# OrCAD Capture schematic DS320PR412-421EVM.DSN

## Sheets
1 PAGE1: title: DS320PR412-421EVM Block; rev: A; note: HSDC110A
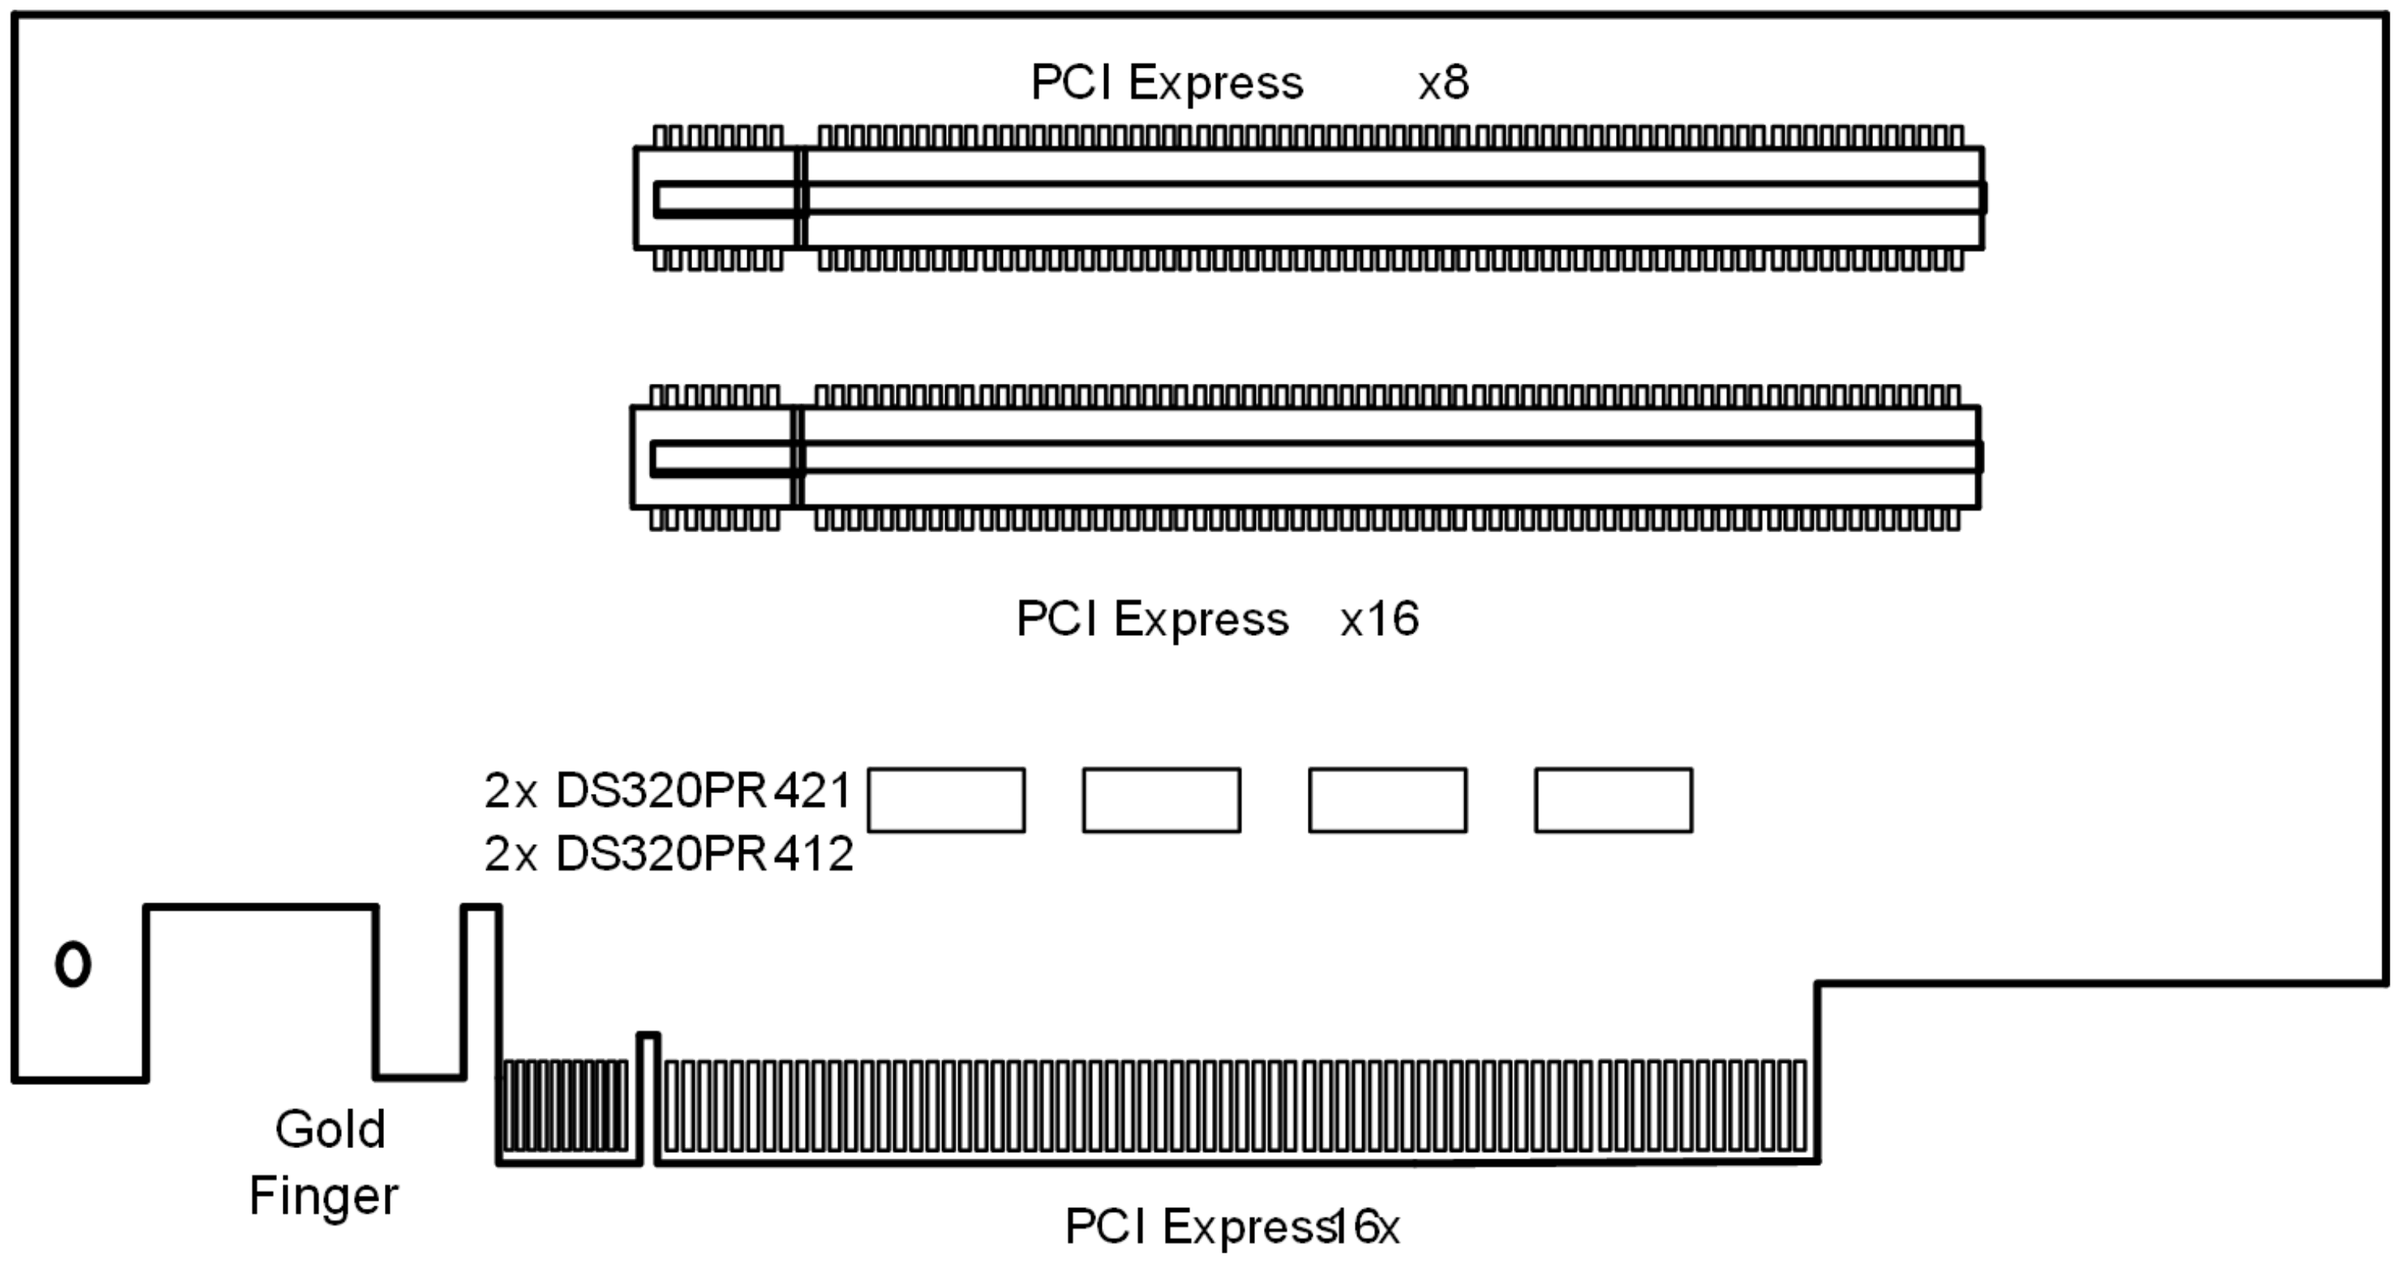
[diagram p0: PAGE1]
2 PAGE10: size C; title: PCIe Connector B x16
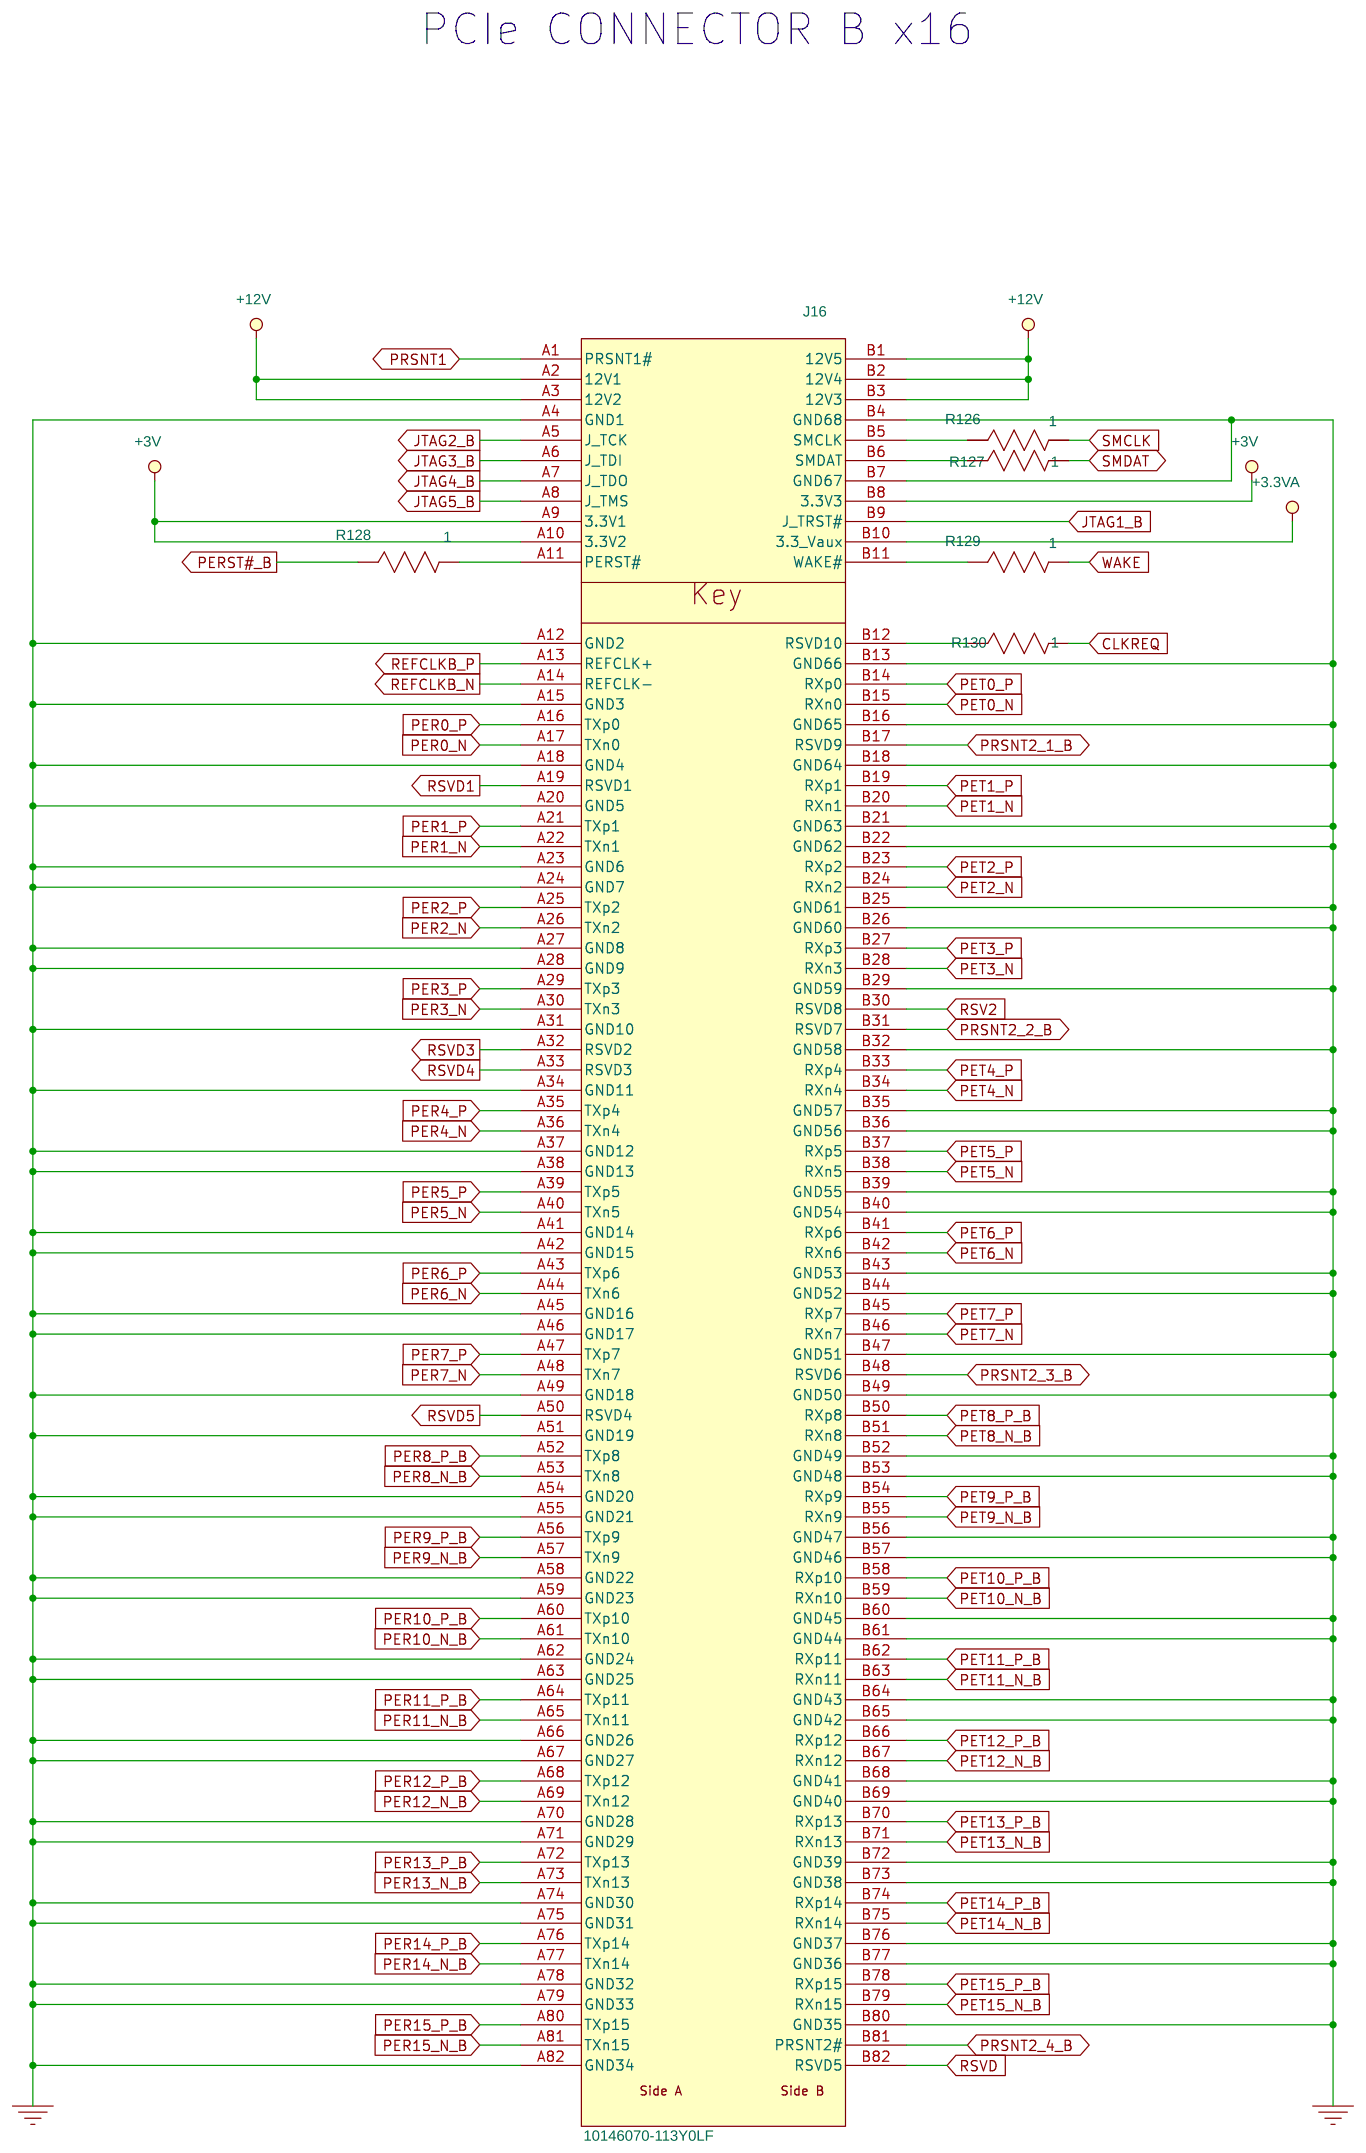
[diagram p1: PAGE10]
3 PAGE11: title: Hardware
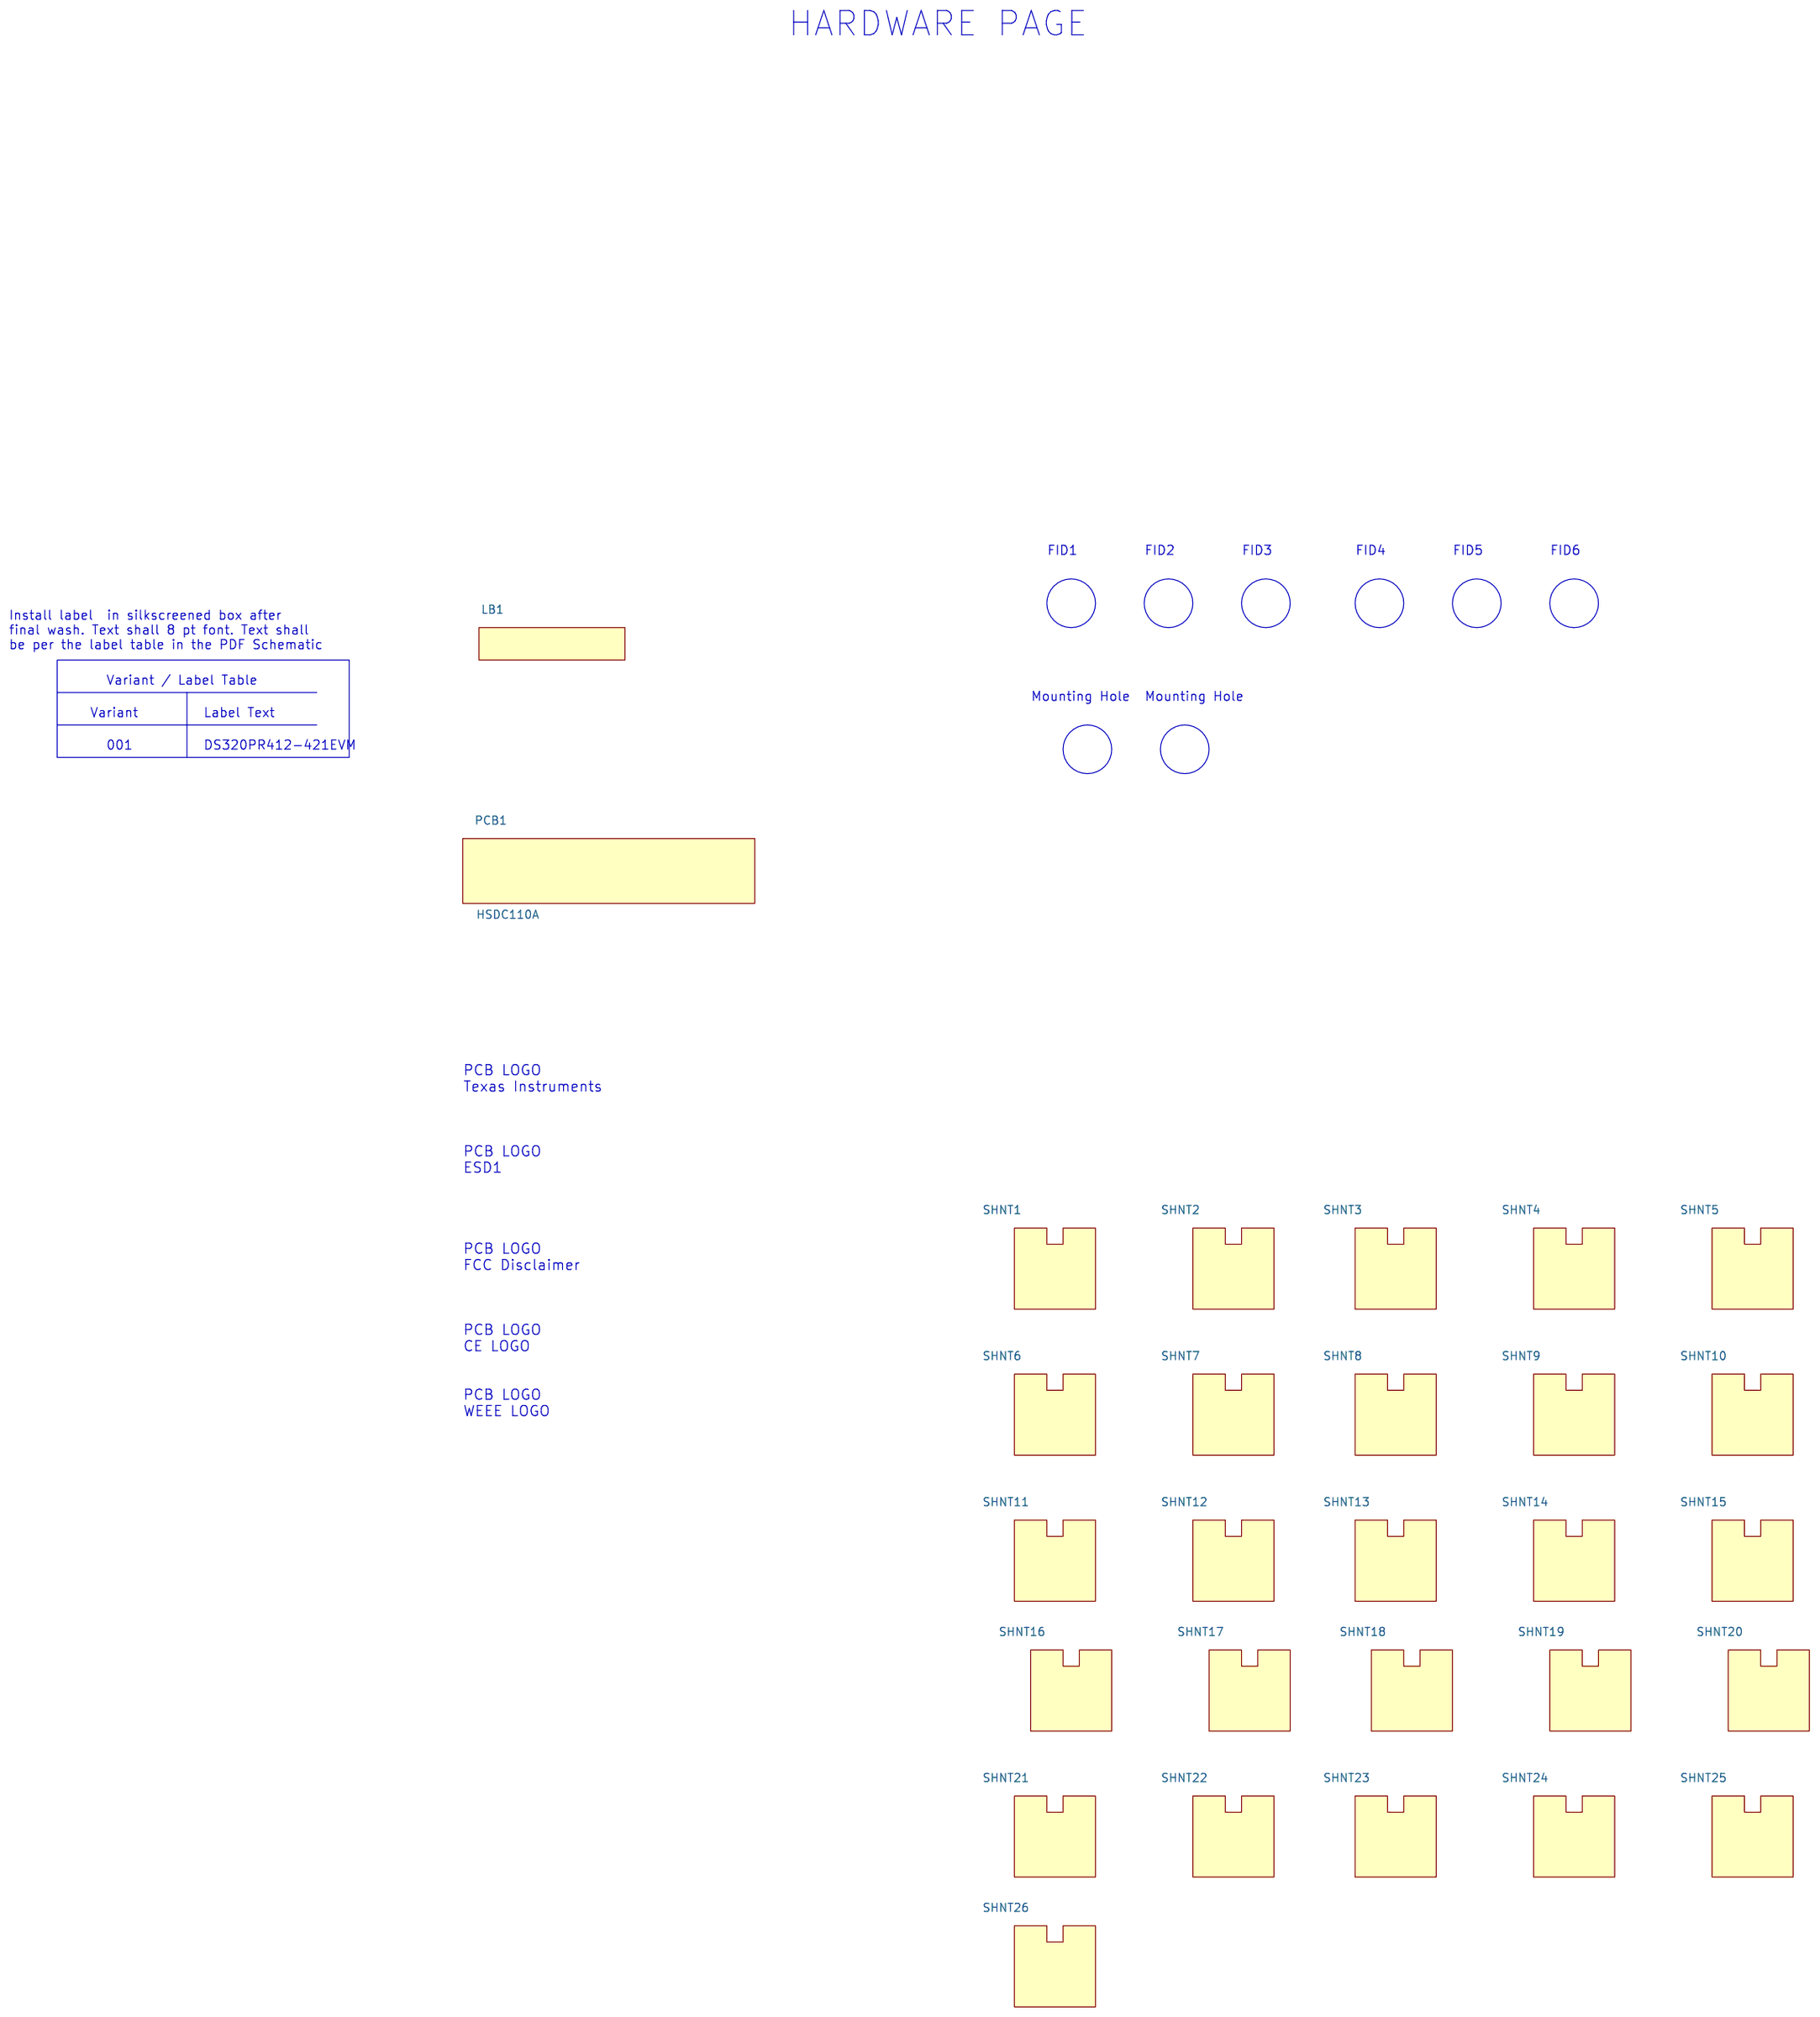
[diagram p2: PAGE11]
4 PAGE2: size C; title: DS320PR412
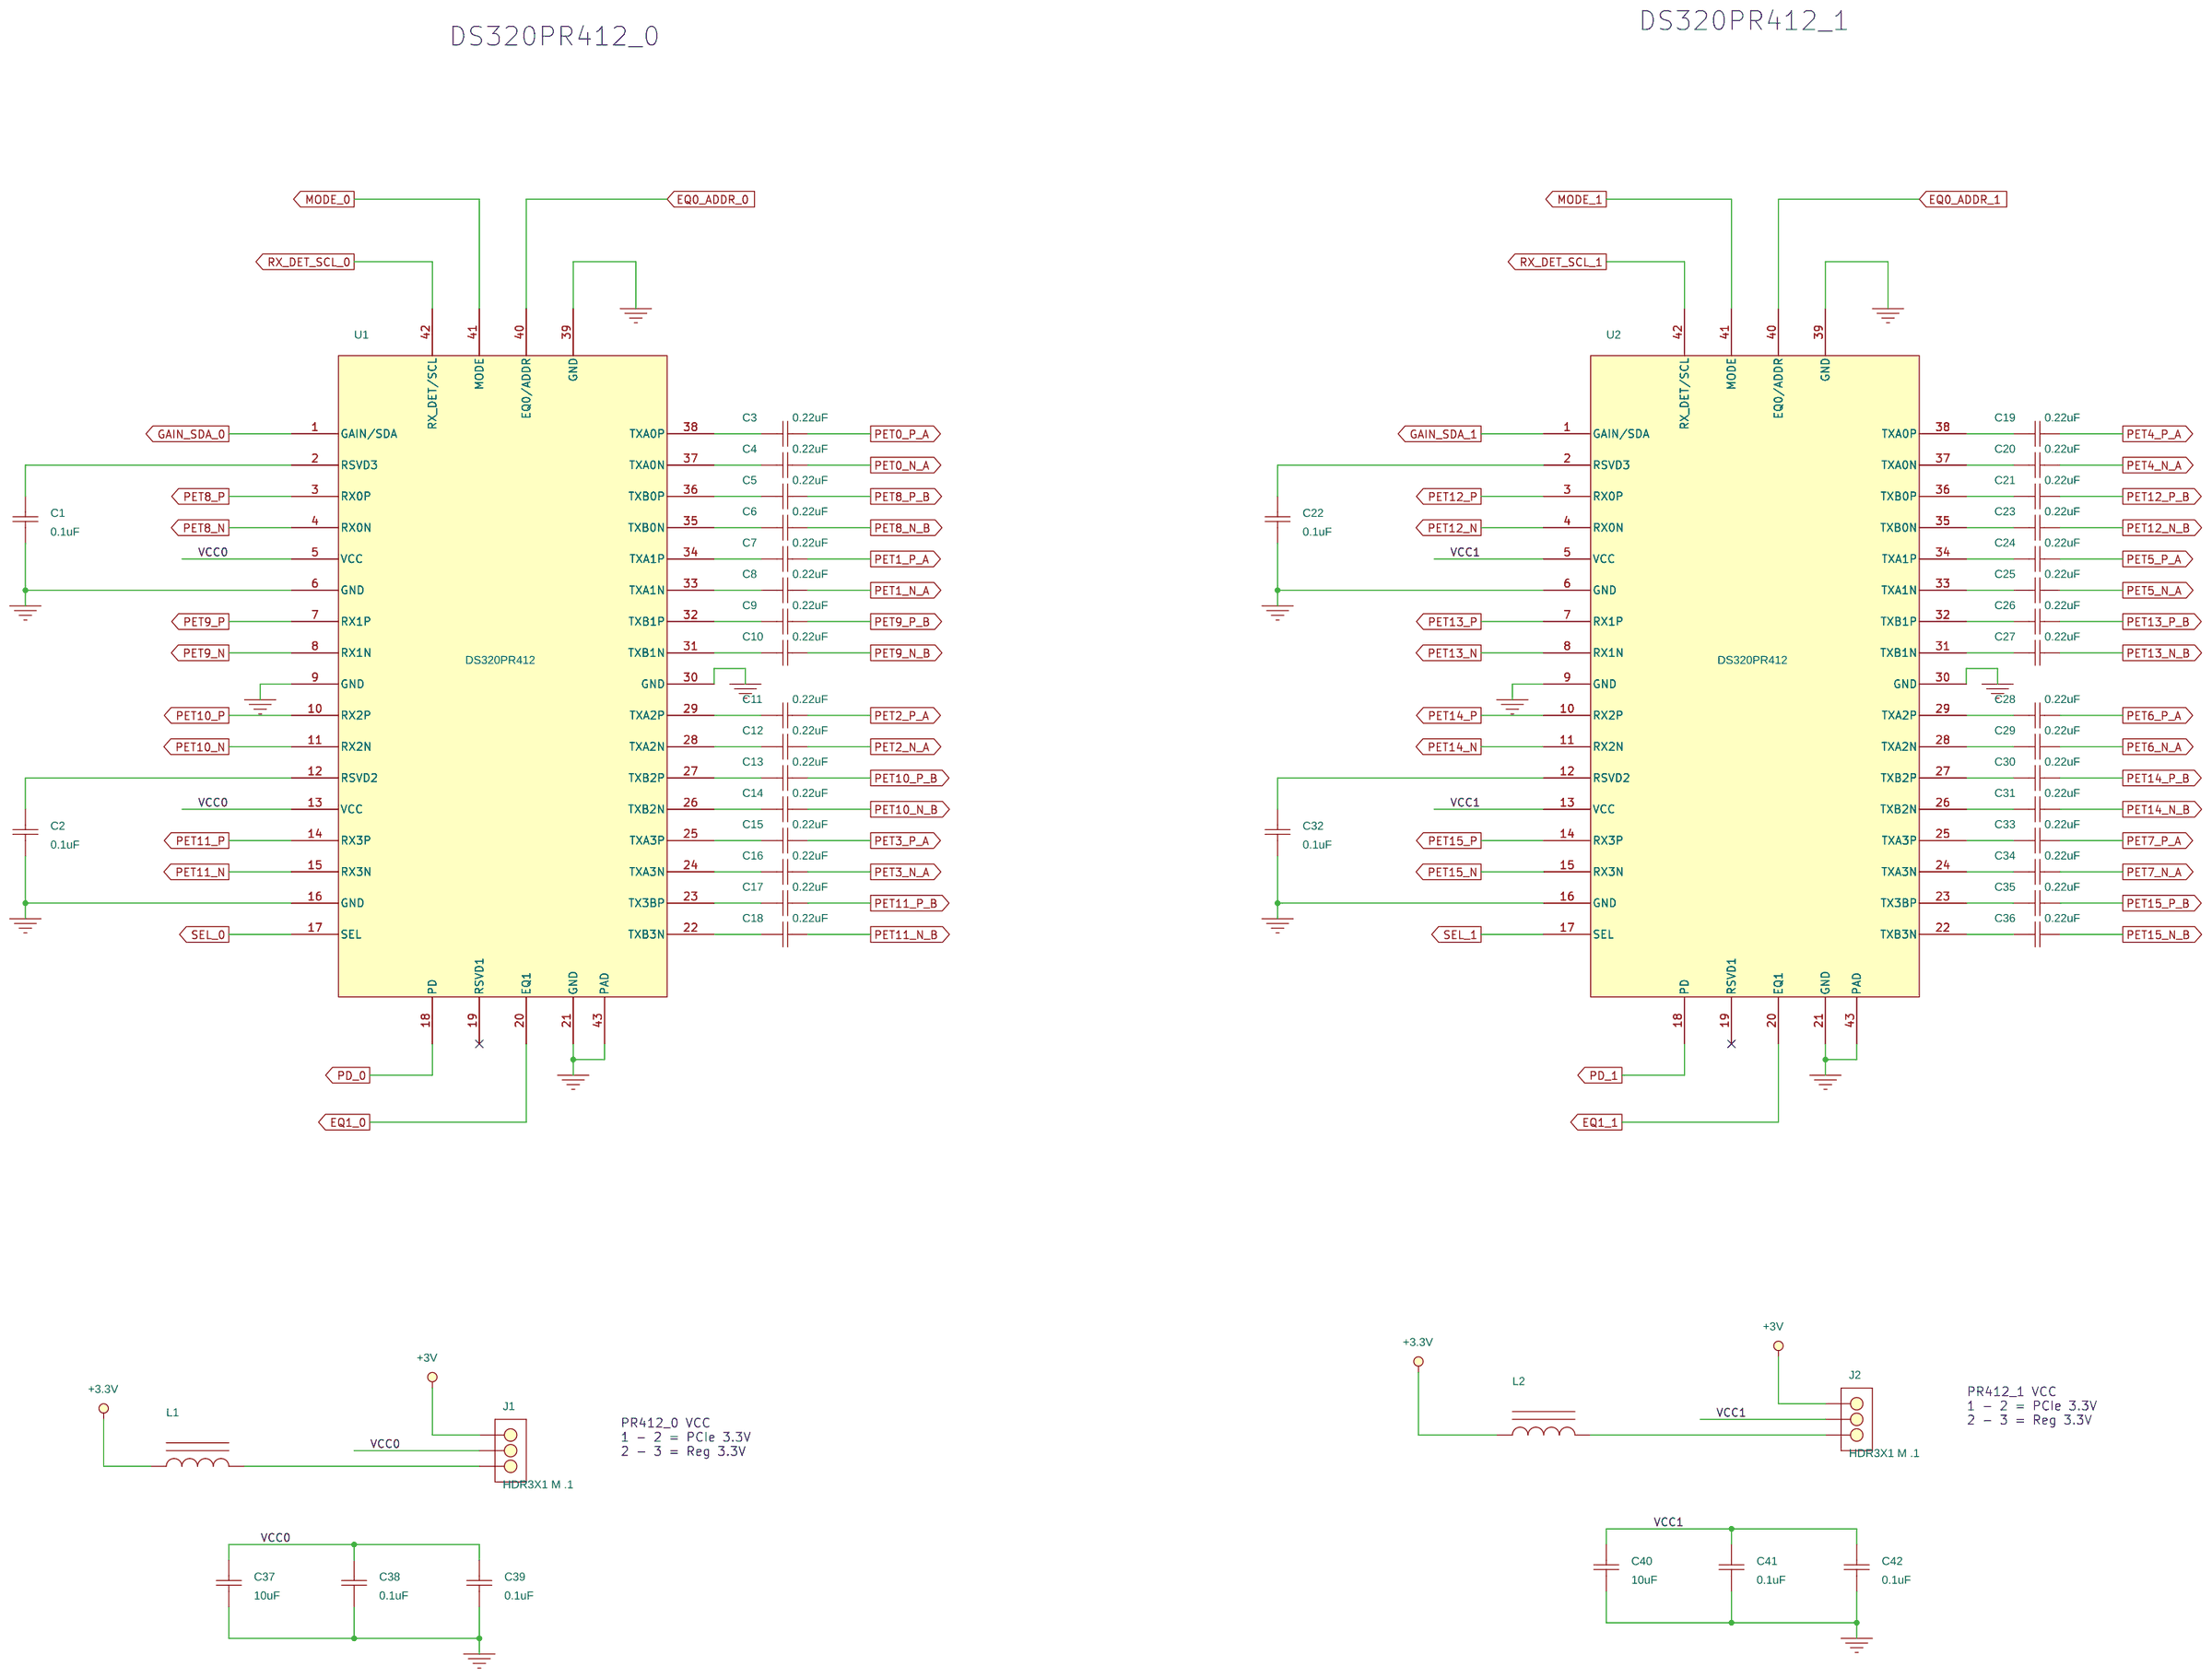
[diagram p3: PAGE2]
5 PAGE3: size C; title: DS320PR421
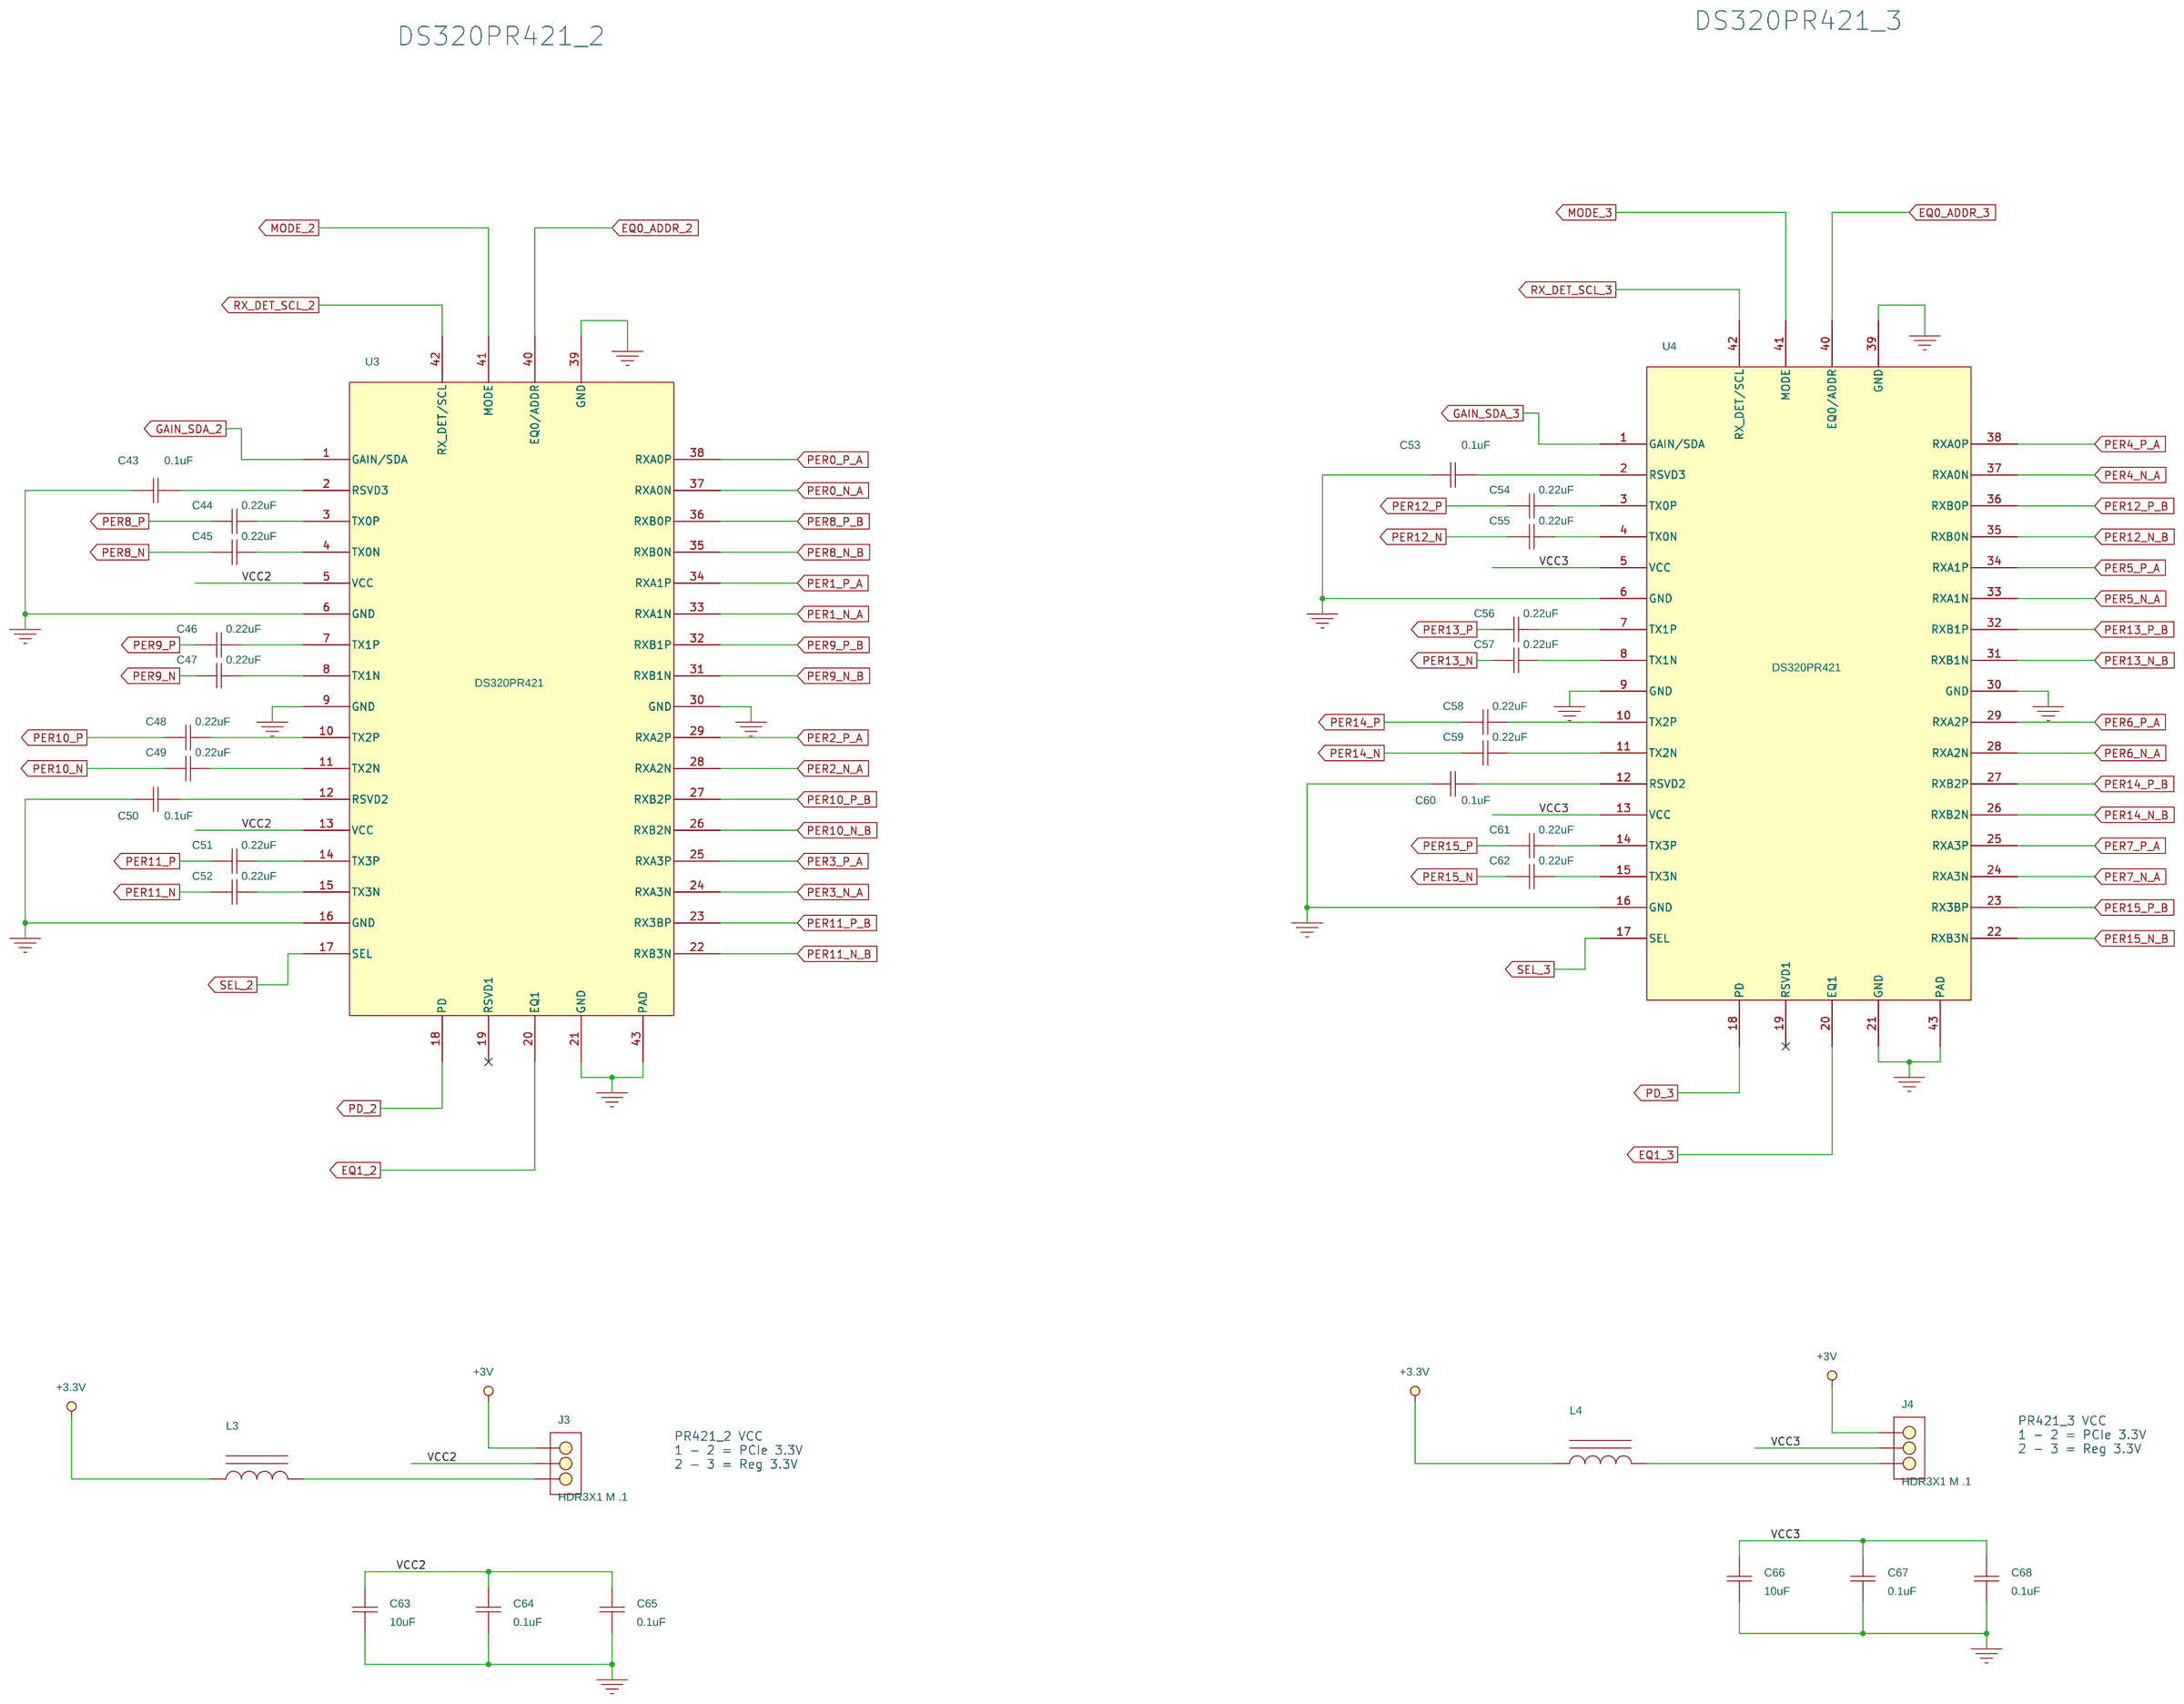
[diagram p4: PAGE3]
6 PAGE4: size C; title: DS320PR412-421 CONFIG
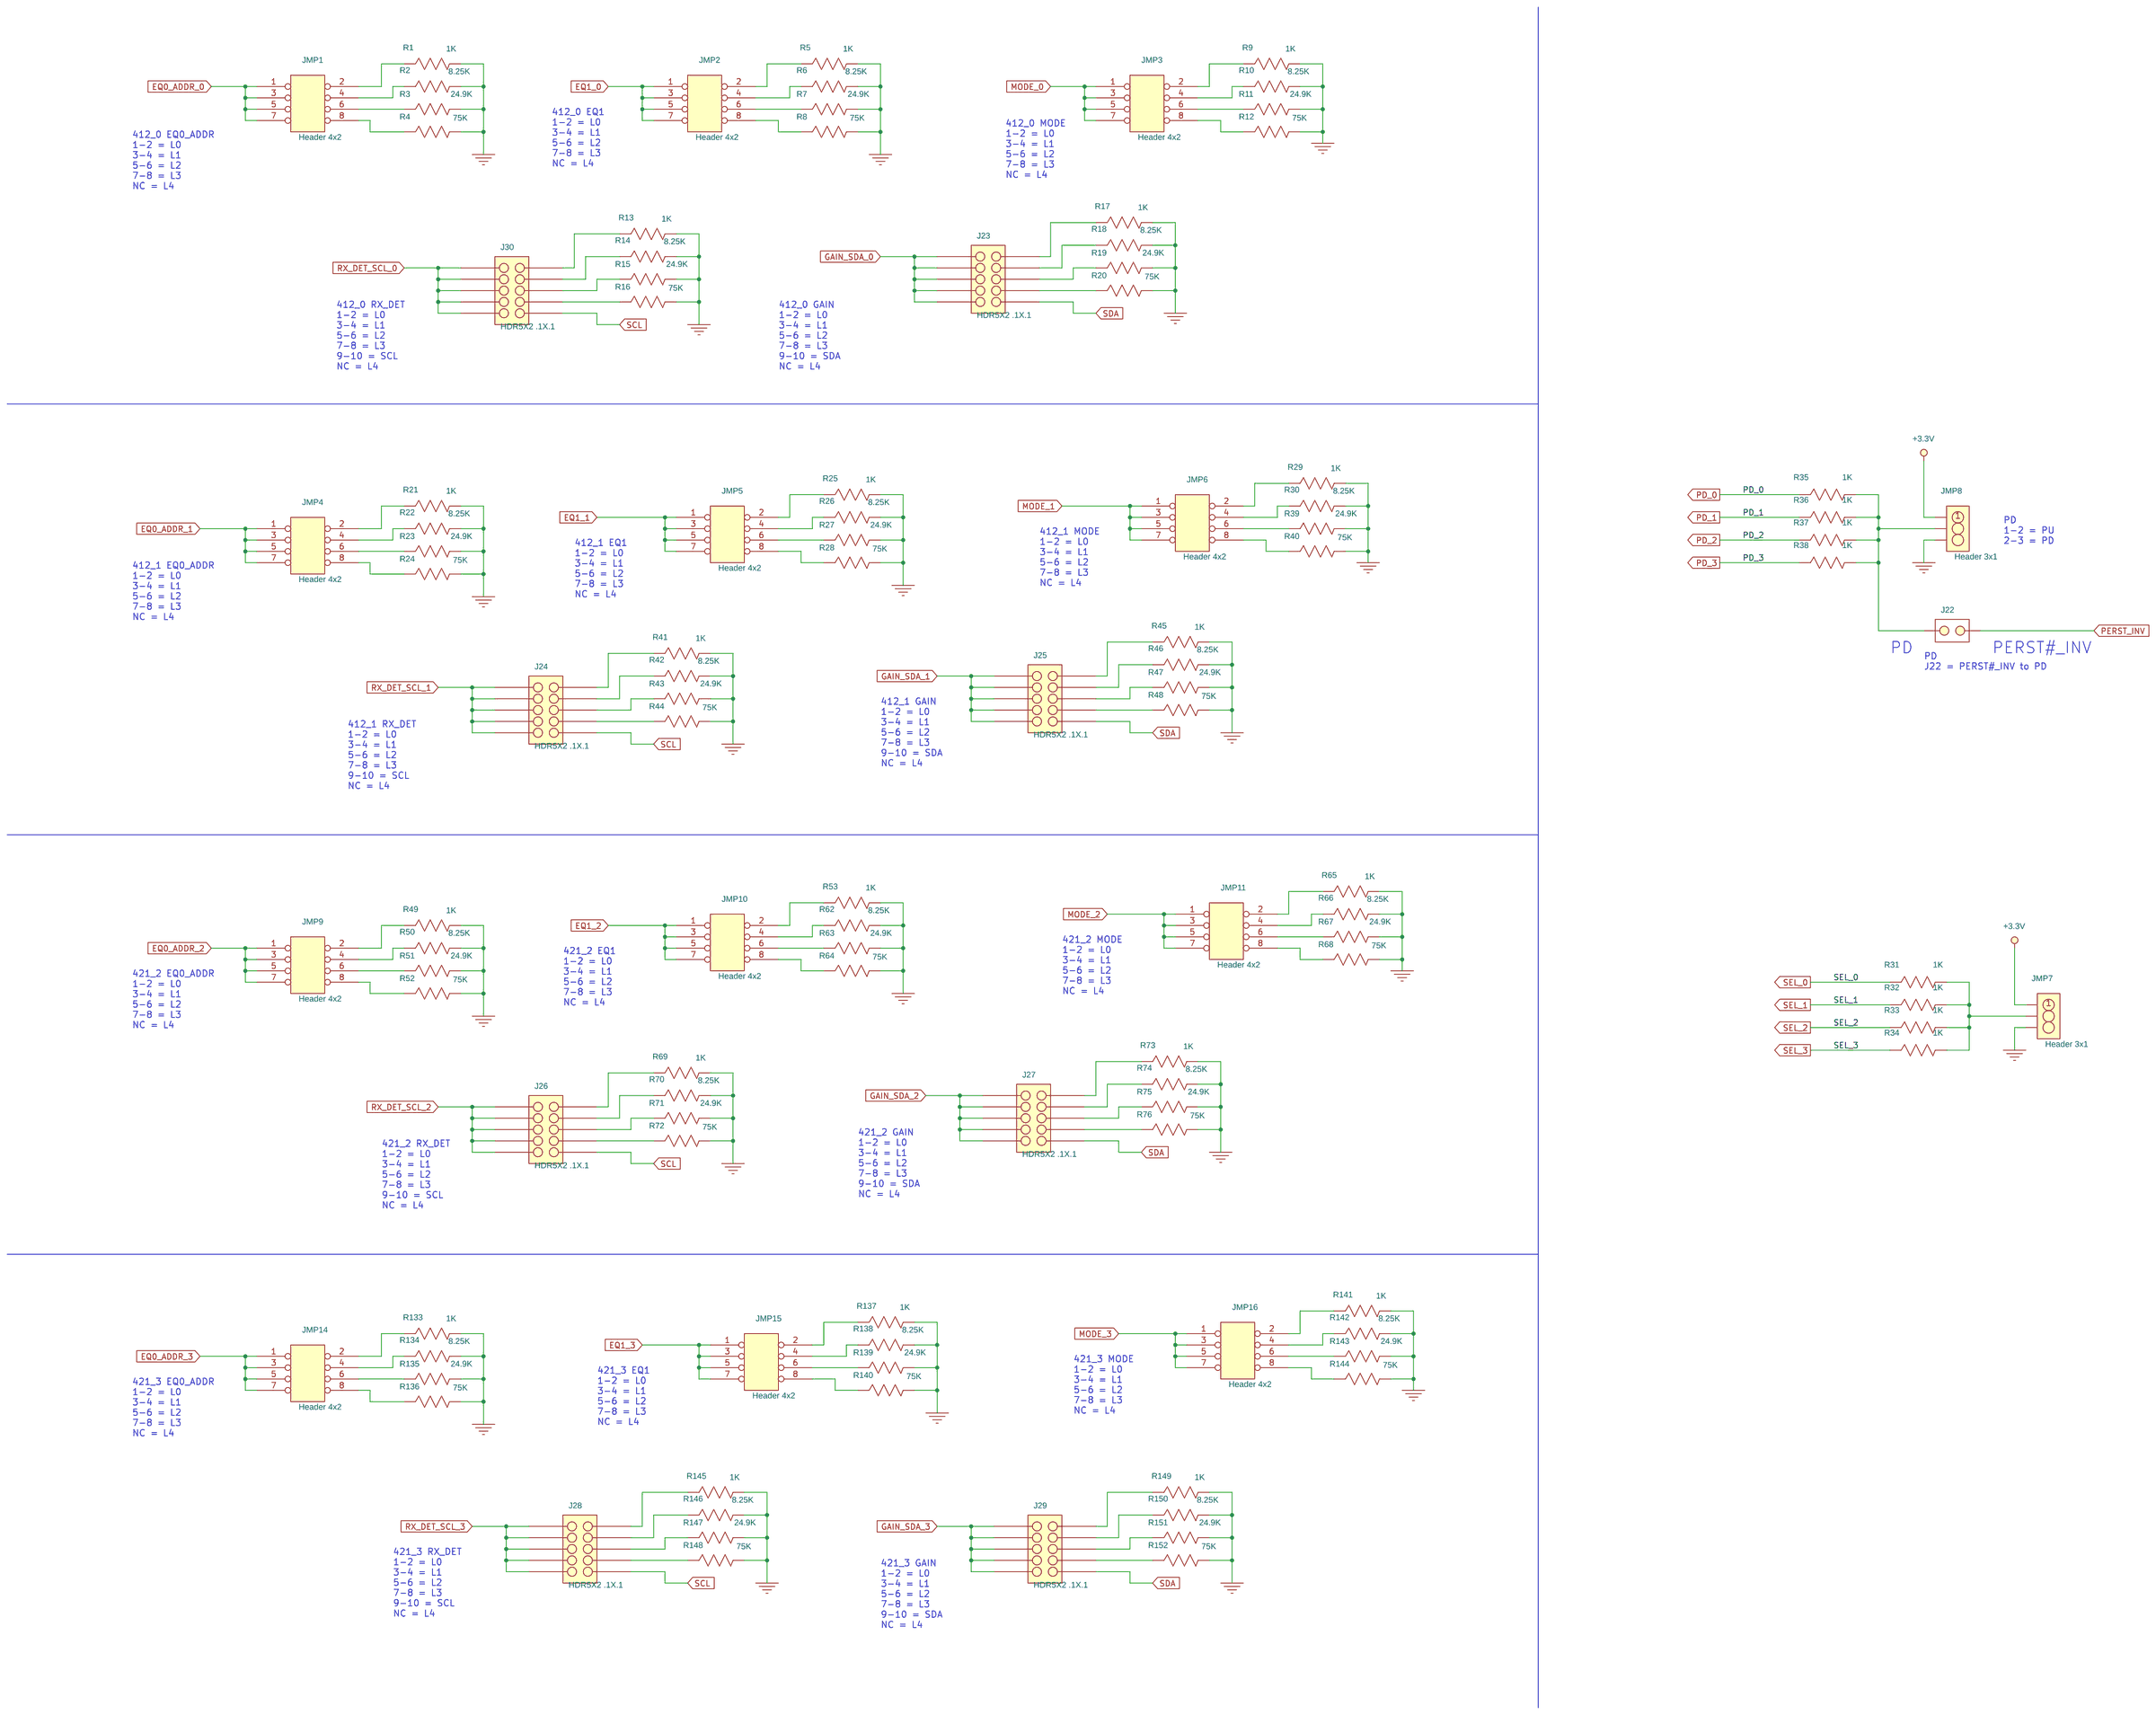
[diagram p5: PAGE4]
7 PAGE5: size C; title: I2C / JTAG
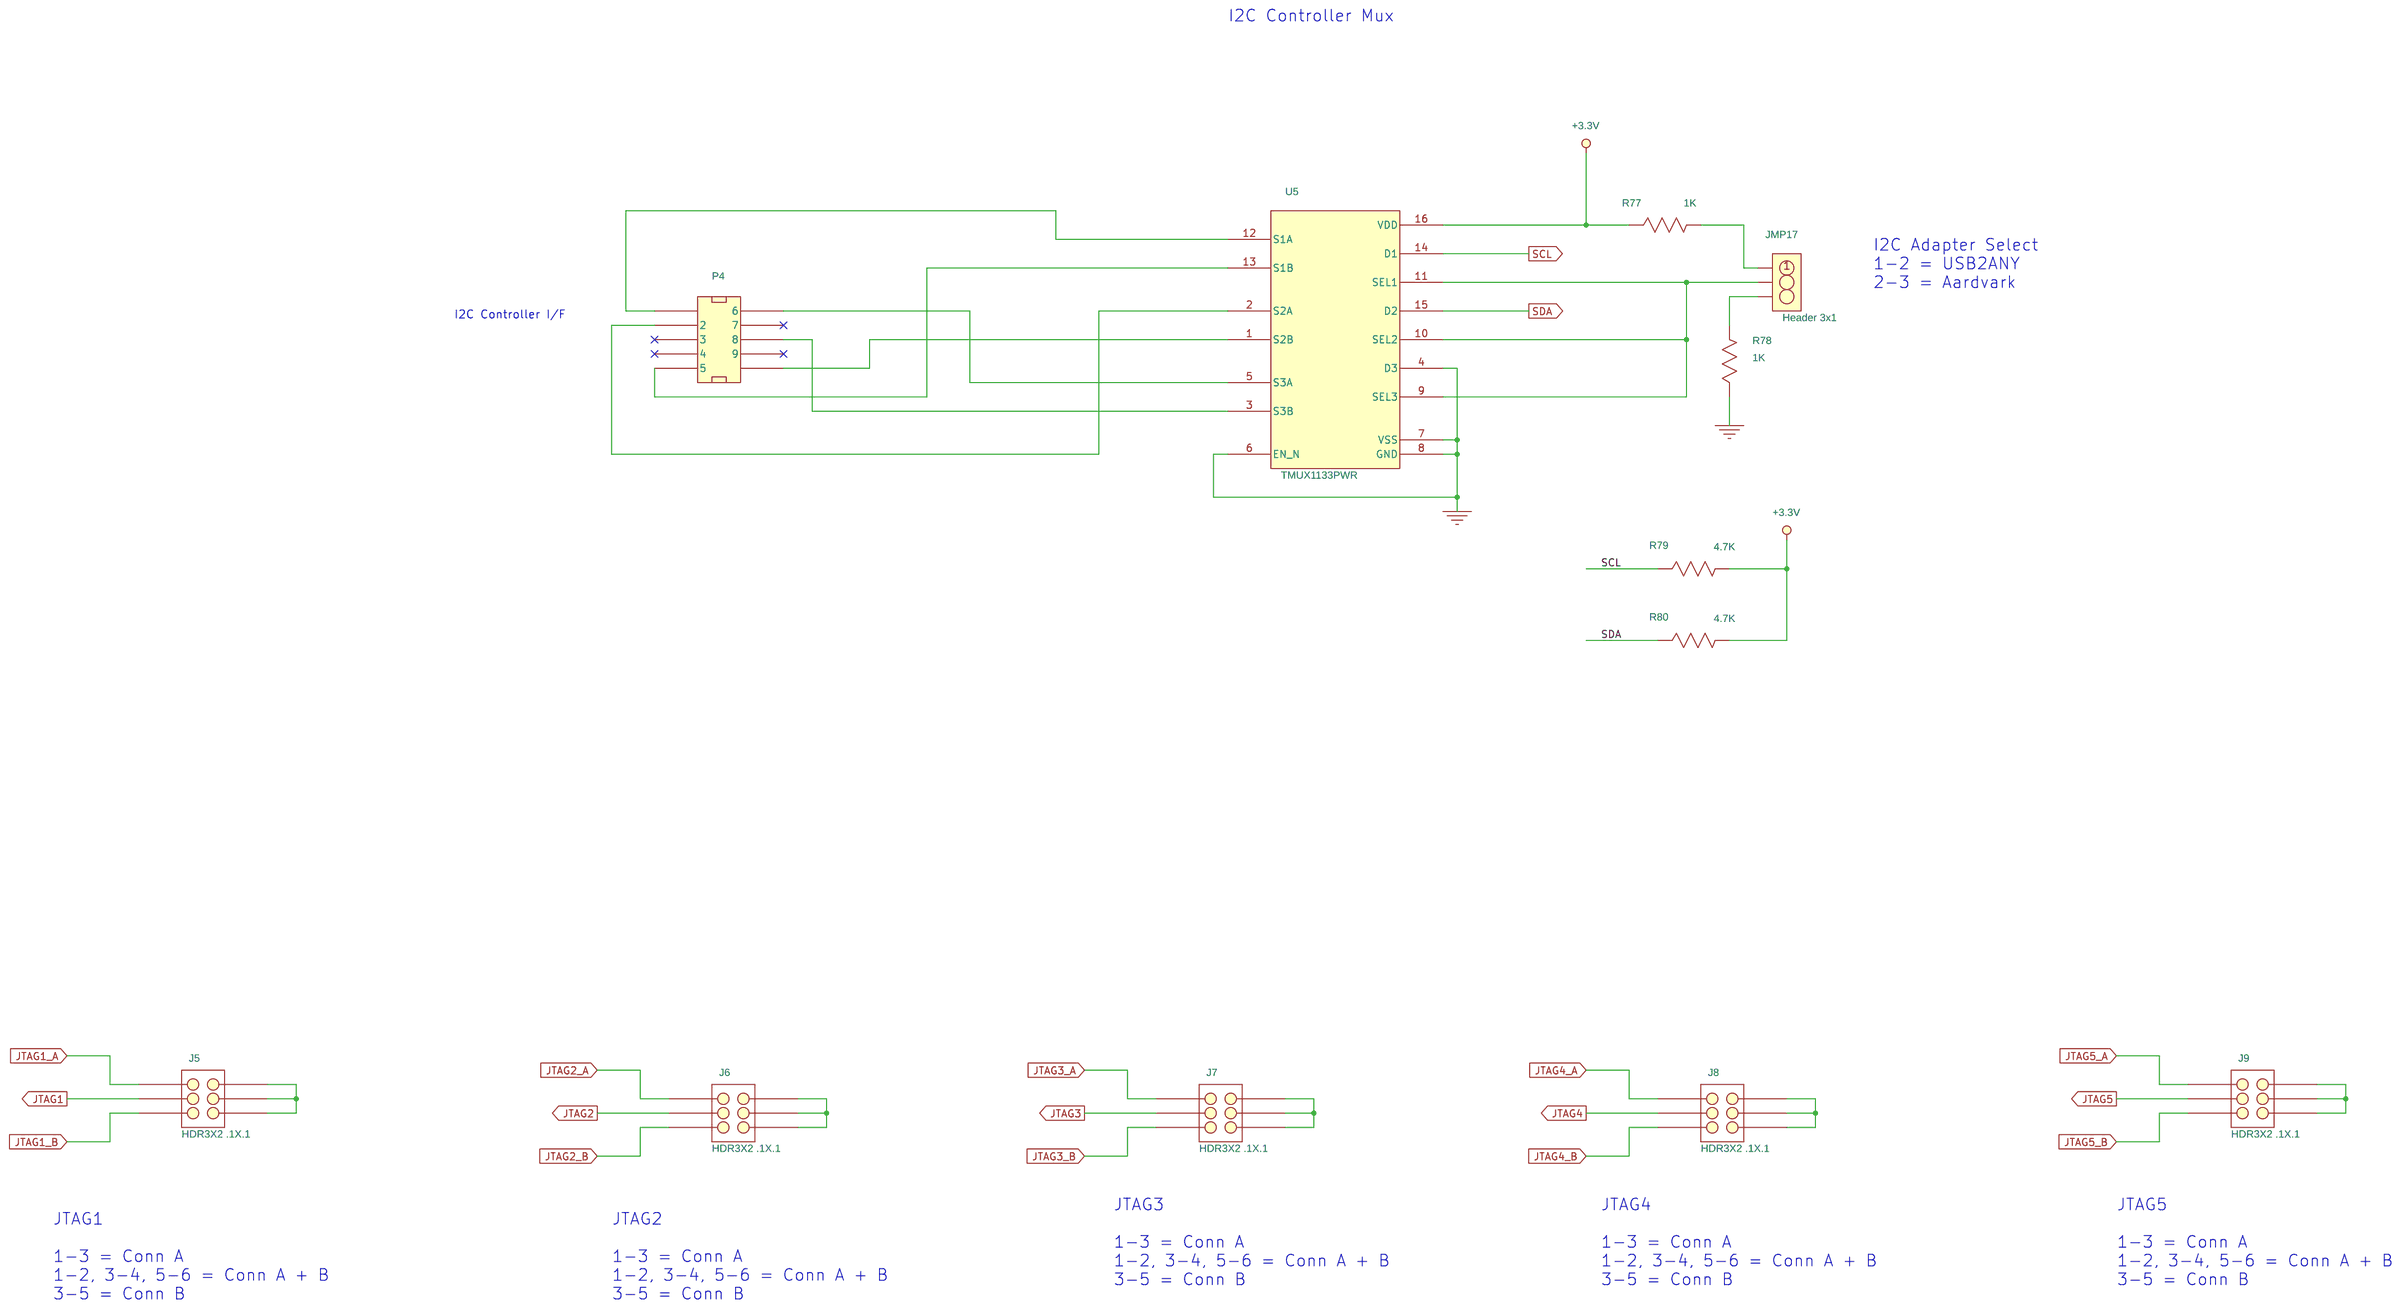
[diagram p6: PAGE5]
8 PAGE6: size C; title: POWER
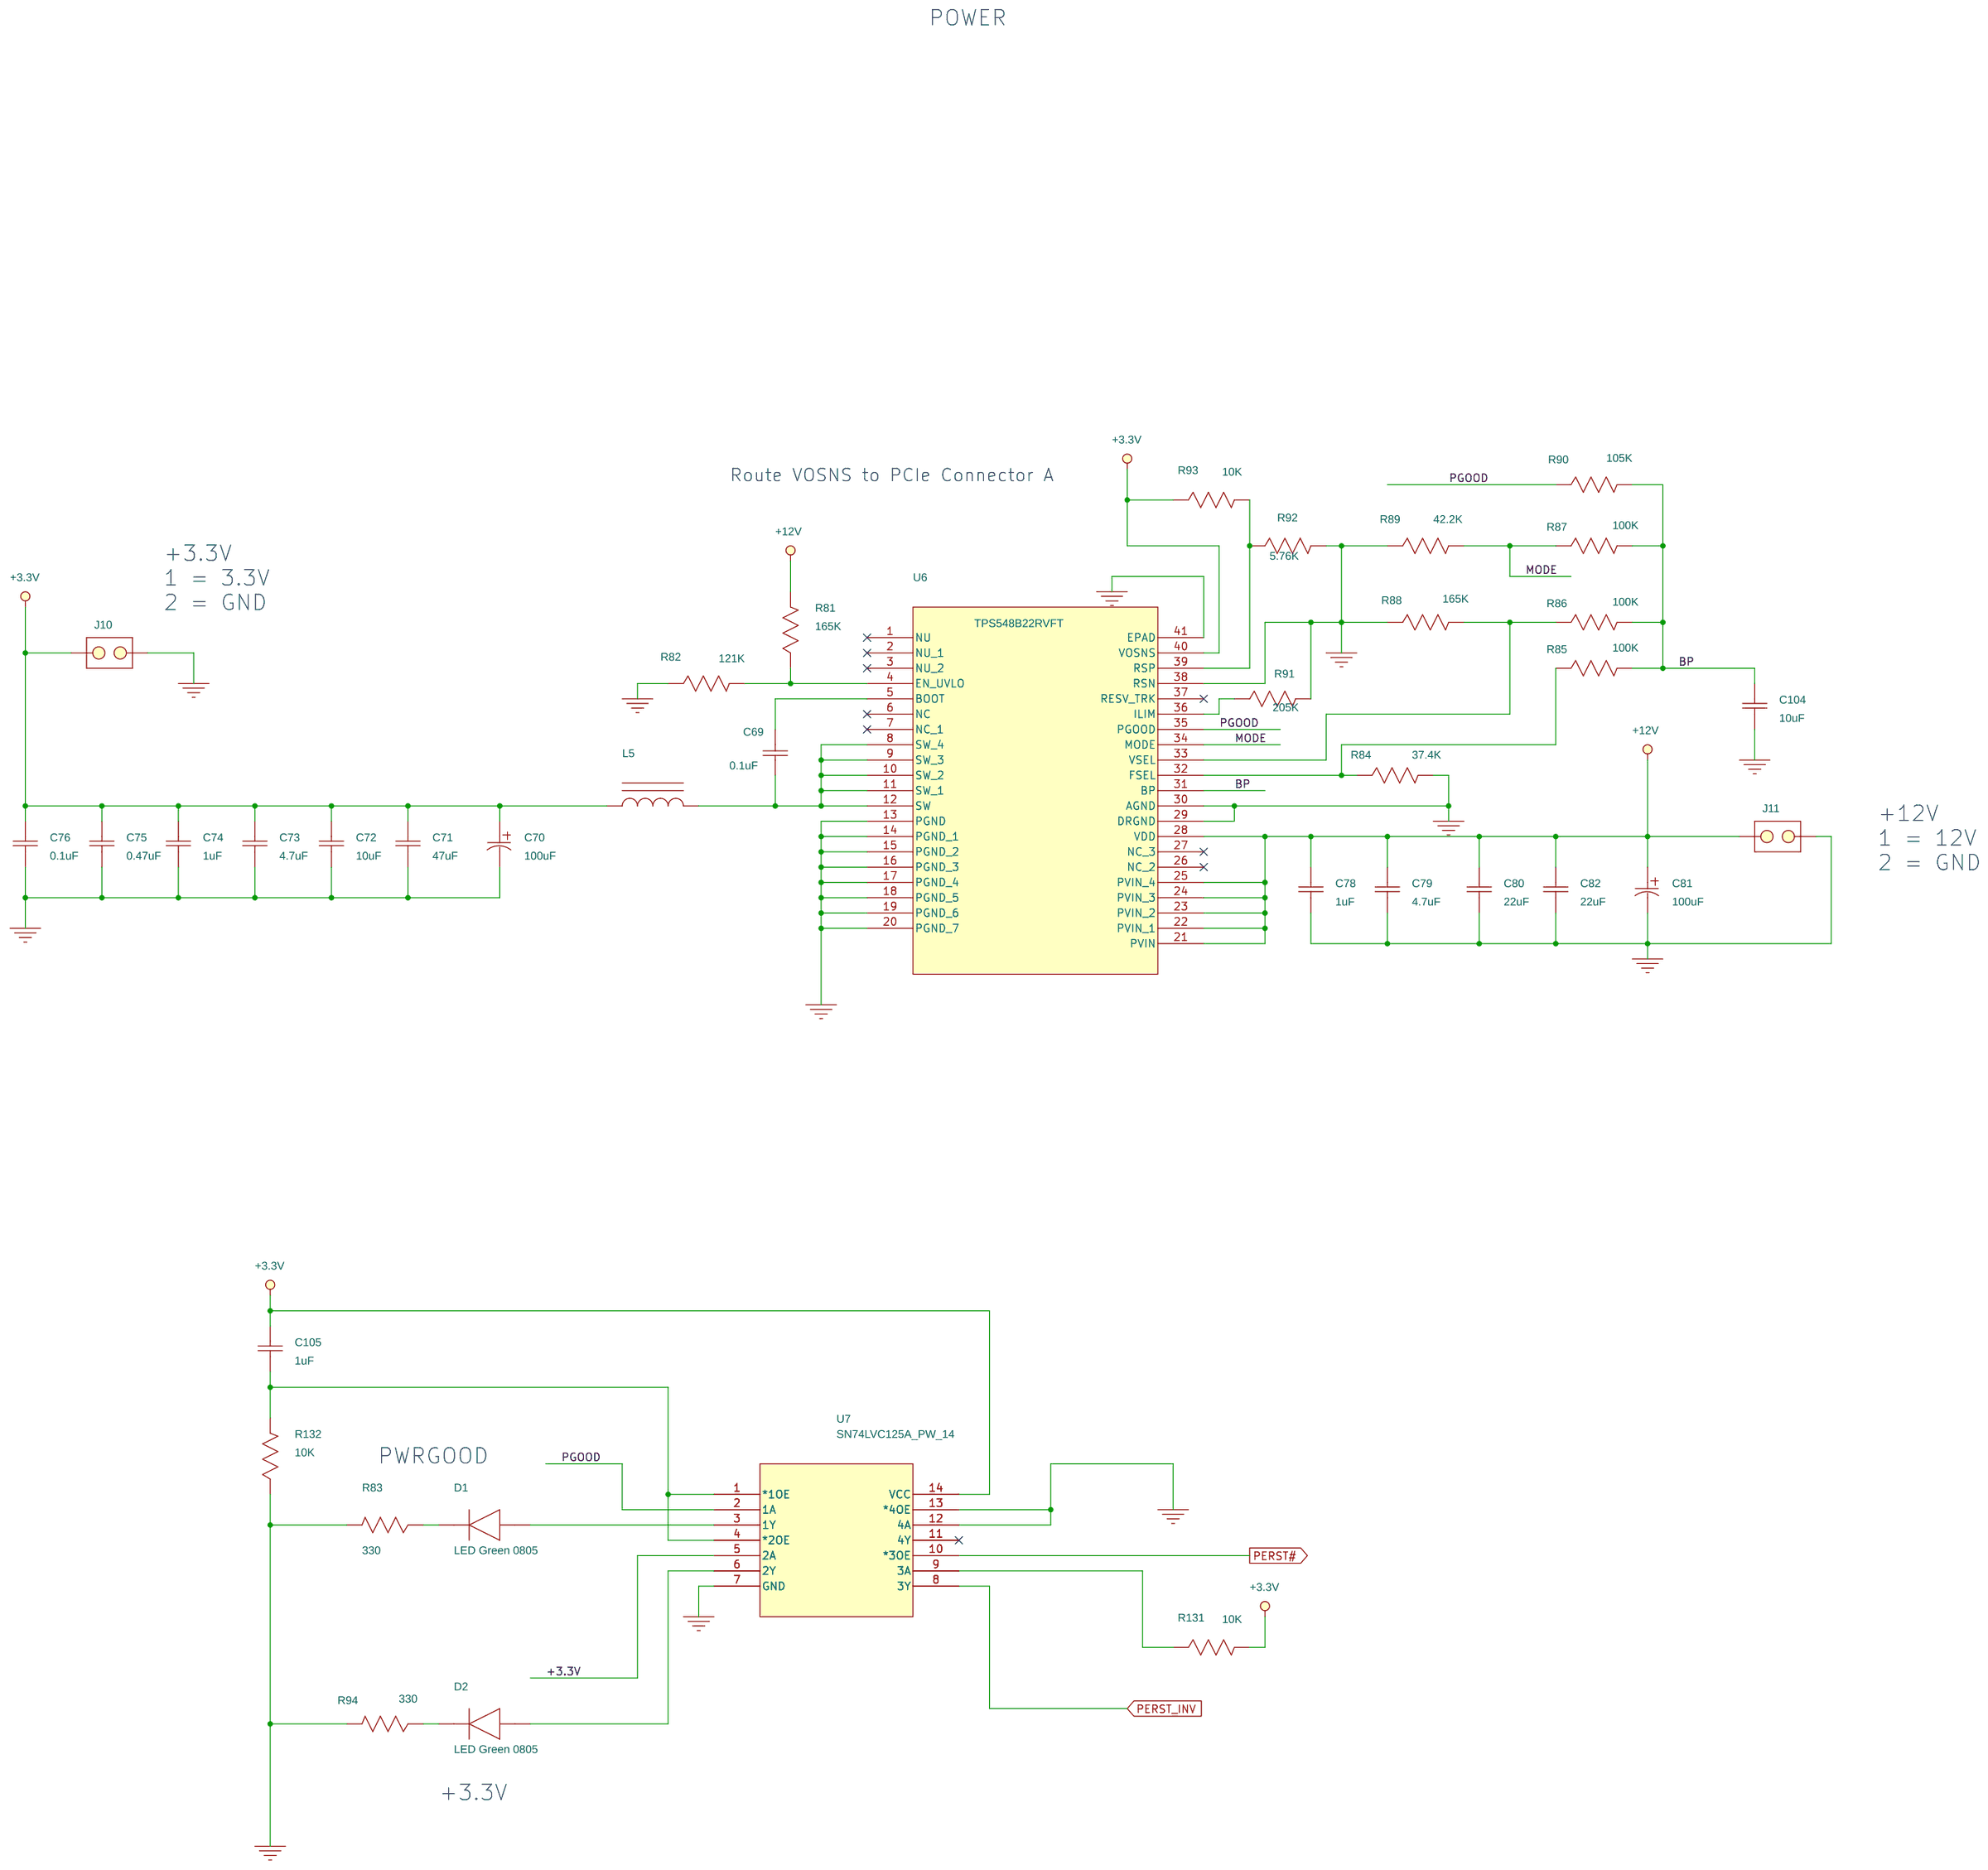
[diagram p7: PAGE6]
9 PAGE7: size C; title: PCIe EDGE Connector
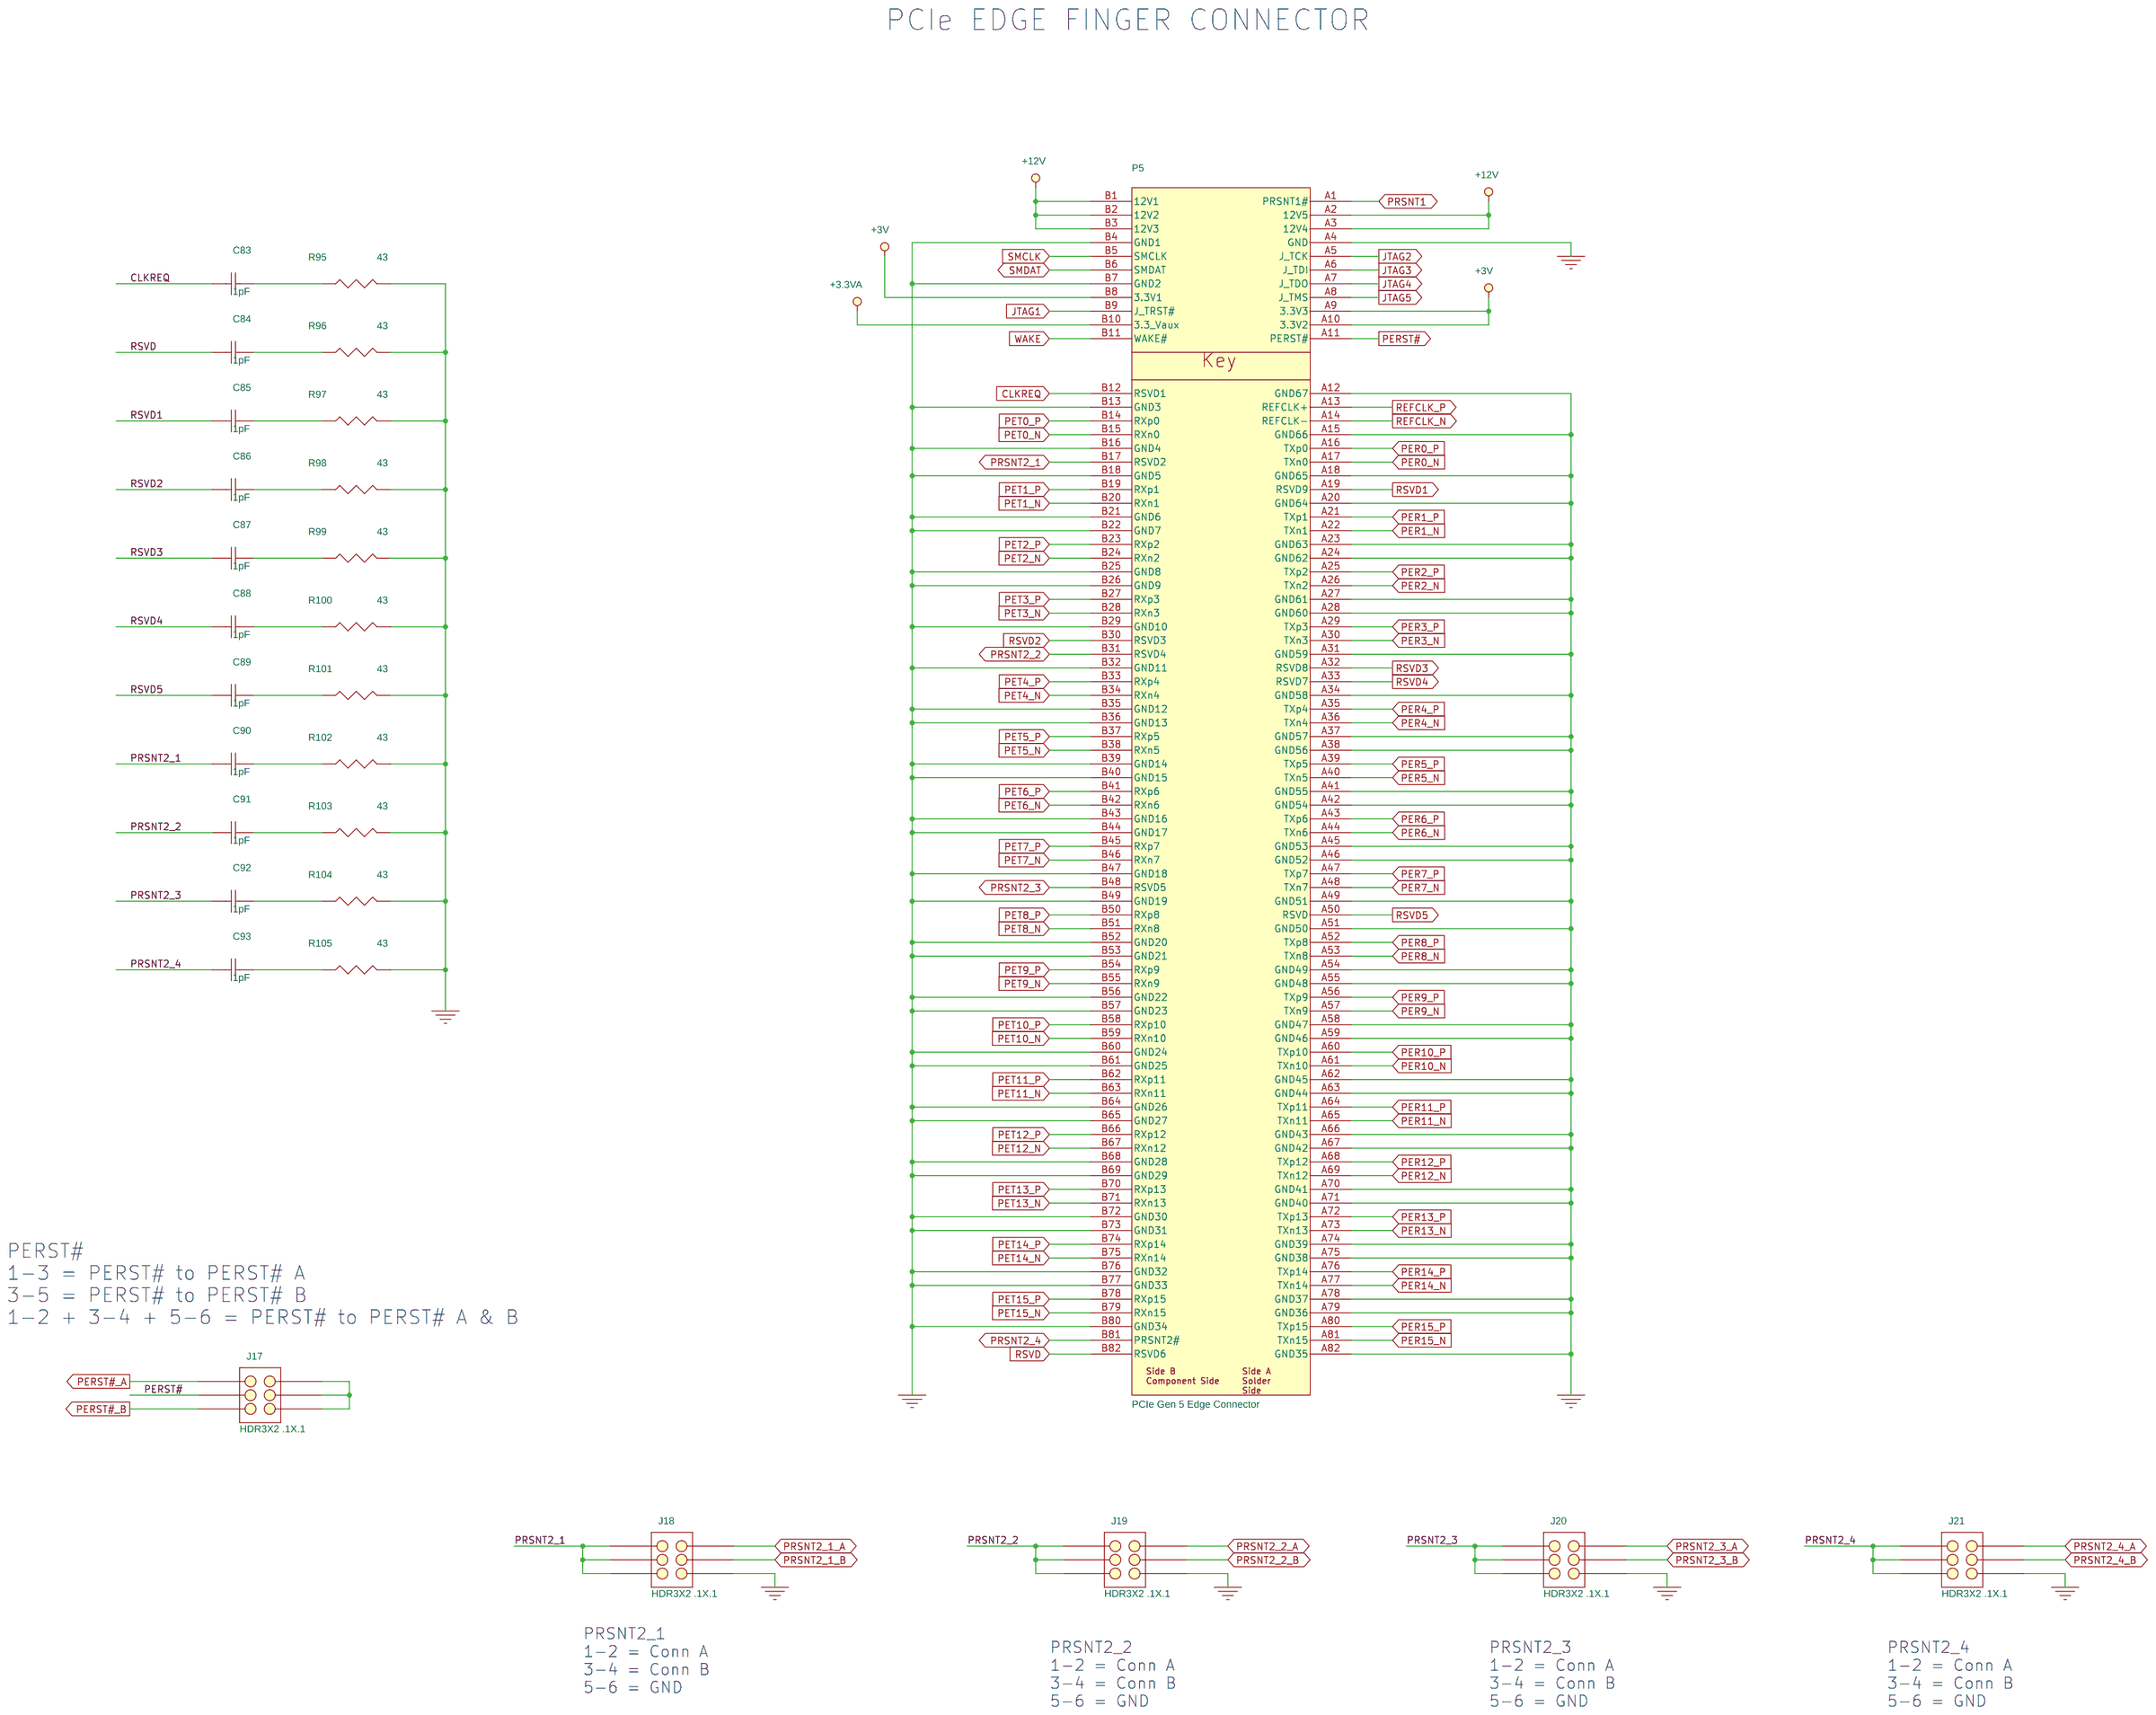
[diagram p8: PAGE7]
10 PAGE8: size C; title: CLK Buffer
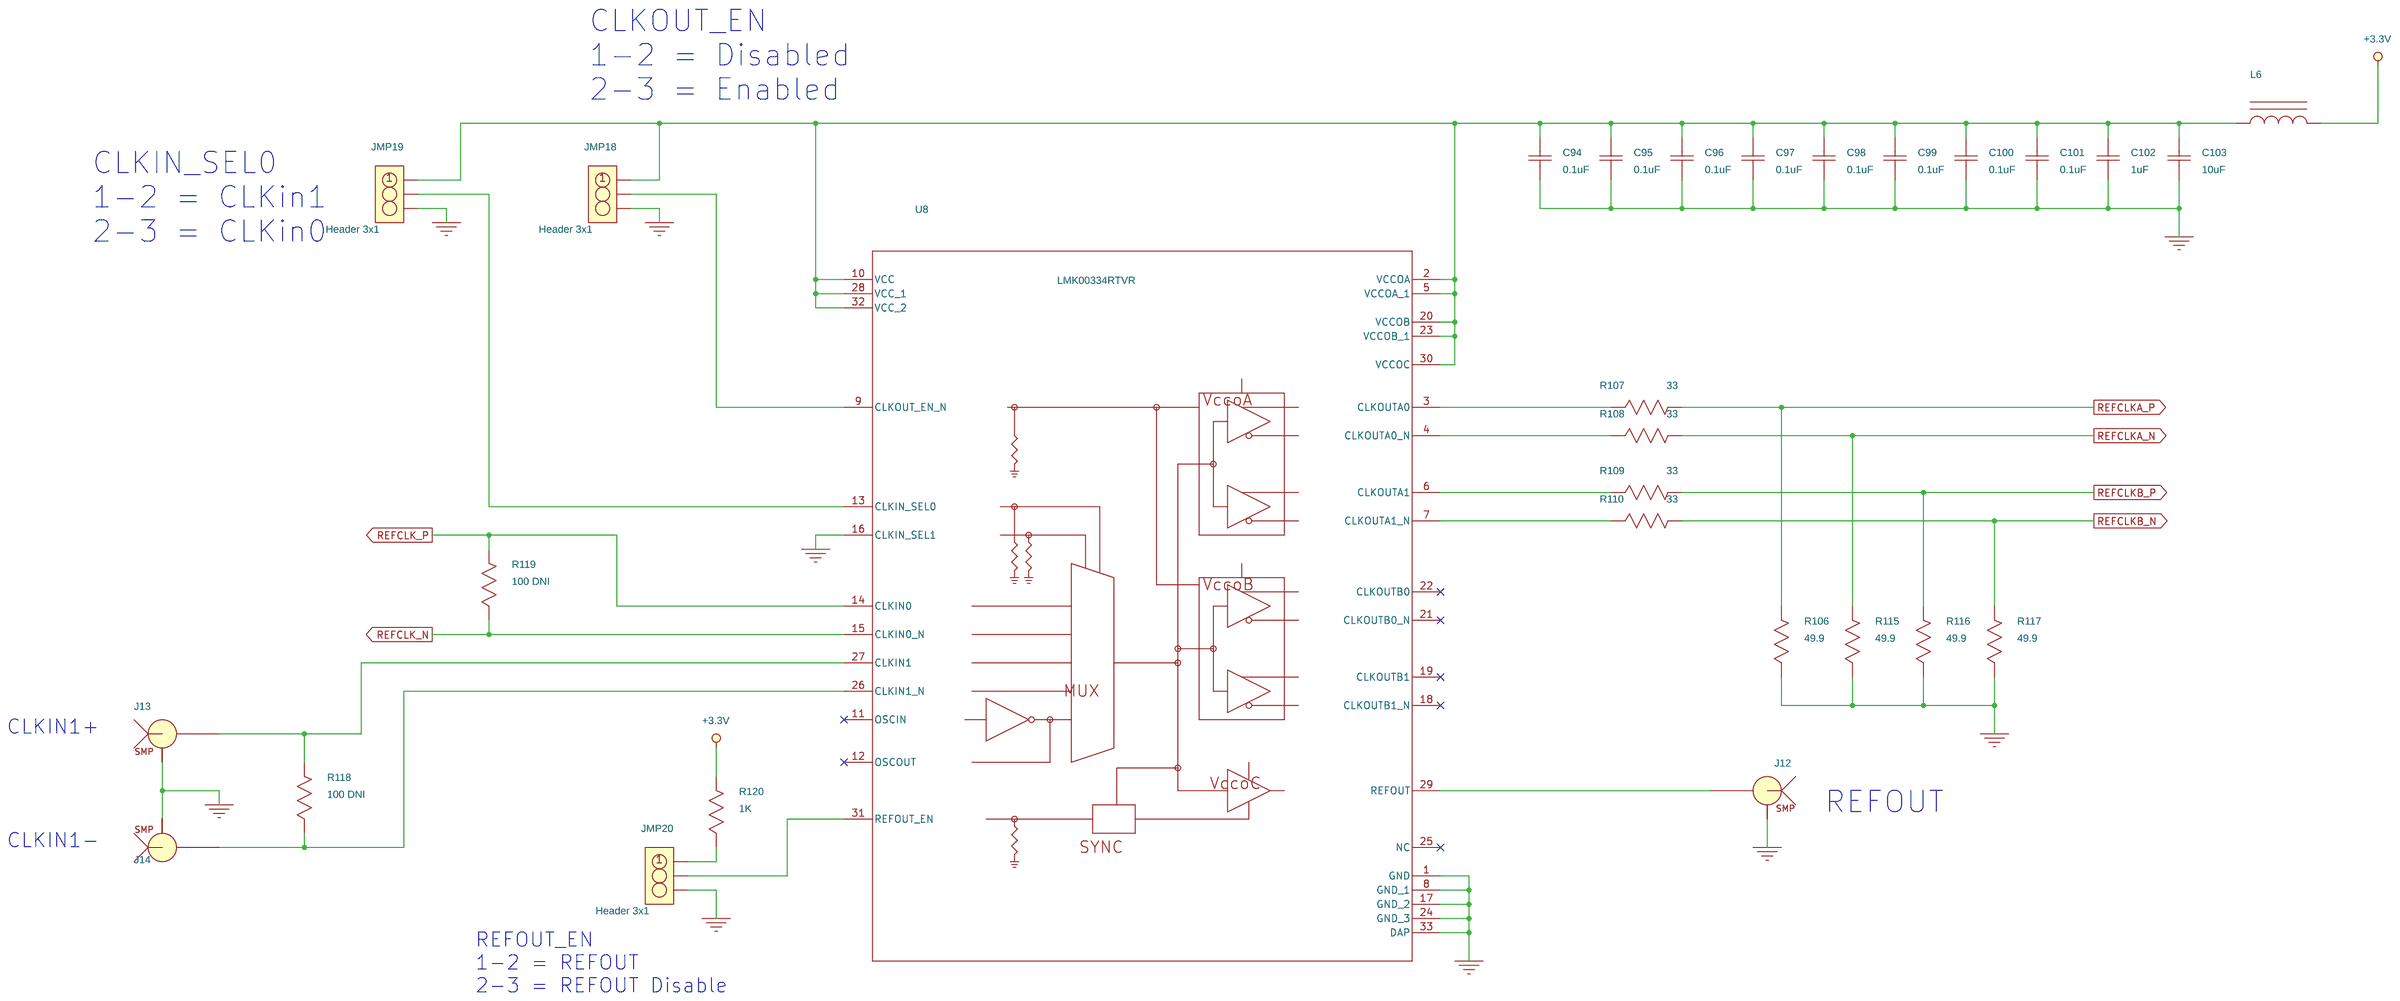
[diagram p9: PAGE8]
11 PAGE9: size C; title: PCIe Connector A x8
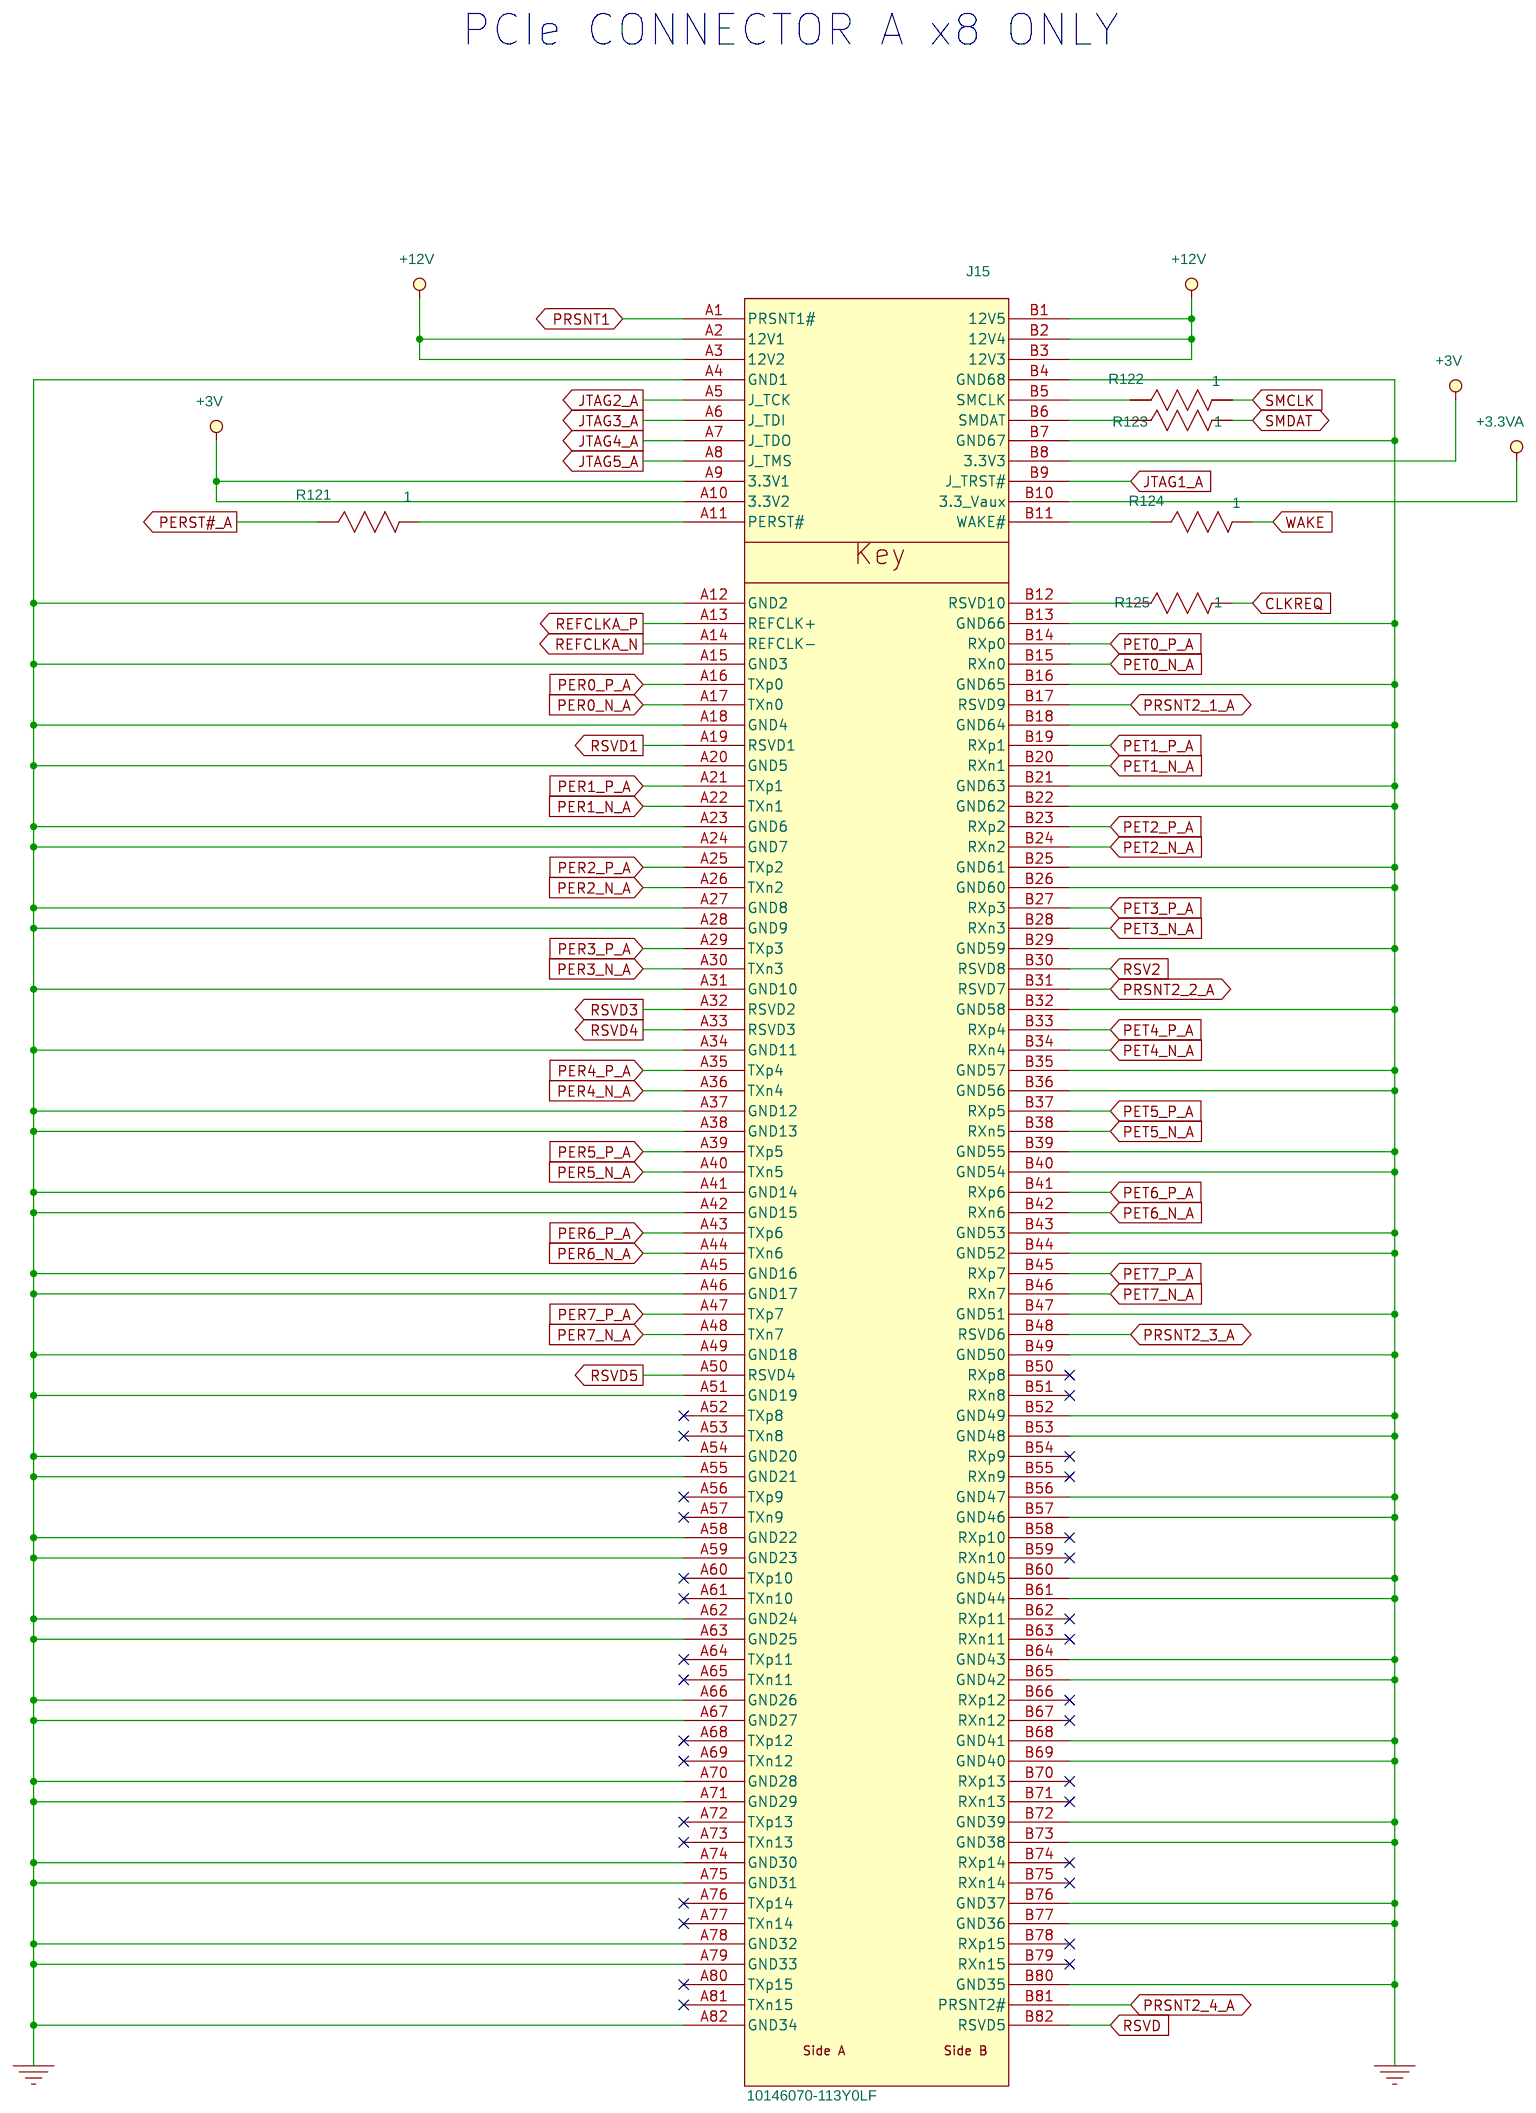
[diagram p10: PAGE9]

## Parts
sheet PAGE2
C1  0.1uF  [CAP_0402]
C2  0.1uF  [CAP_0402]
C3  0.22uF  [CAP_0201]
C4  0.22uF  [CAP_0201]
C5  0.22uF  [CAP_0201]
C6  0.22uF  [CAP_0201]
C7  0.22uF  [CAP_0201]
C8  0.22uF  [CAP_0201]
C9  0.22uF  [CAP_0201]
C10  0.22uF  [CAP_0201]
C11  0.22uF  [CAP_0201]
C12  0.22uF  [CAP_0201]
C13  0.22uF  [CAP_0201]
C14  0.22uF  [CAP_0201]
C15  0.22uF  [CAP_0201]
C16  0.22uF  [CAP_0201]
C17  0.22uF  [CAP_0201]
C18  0.22uF  [CAP_0201]
C19  0.22uF  [CAP_0201]
C20  0.22uF  [CAP_0201]
C21  0.22uF  [CAP_0201]
C22  0.1uF  [CAP_0402]
C23  0.22uF  [CAP_0201]
C24  0.22uF  [CAP_0201]
C25  0.22uF  [CAP_0201]
C26  0.22uF  [CAP_0201]
C27  0.22uF  [CAP_0201]
C28  0.22uF  [CAP_0201]
C29  0.22uF  [CAP_0201]
C30  0.22uF  [CAP_0201]
C31  0.22uF  [CAP_0201]
C32  0.1uF  [CAP_0402]
C33  0.22uF  [CAP_0201]
C34  0.22uF  [CAP_0201]
C35  0.22uF  [CAP_0201]
C36  0.22uF  [CAP_0201]
C37  10uF  [CAP_0603]
C38  0.1uF  [CAP_0402]
C39  0.1uF  [CAP_0402]
C40  10uF  [CAP_0603]
C41  0.1uF  [CAP_0402]
C42  0.1uF  [CAP_0402]
J1  HDR3X1 M .1  [HDR_THVT_1x3_254_838]
J2  HDR3X1 M .1  [HDR_THVT_1x3_254_838]
L1  6.8uH  [IND_SM_DRA73]
L2  6.8uH  [IND_SM_DRA73]
U1  DS320PR412  [RUA0042BA_205X755]
U2  DS320PR412  [RUA0042BA_205X755]
sheet PAGE3
C43  0.1uF  [CAP_0402]
C44  0.22uF  [CAP_0201]
C45  0.22uF  [CAP_0201]
C46  0.22uF  [CAP_0201]
C47  0.22uF  [CAP_0201]
C48  0.22uF  [CAP_0201]
C49  0.22uF  [CAP_0201]
C50  0.1uF  [CAP_0402]
C51  0.22uF  [CAP_0201]
C52  0.22uF  [CAP_0201]
C53  0.1uF  [CAP_0402]
C54  0.22uF  [CAP_0201]
C55  0.22uF  [CAP_0201]
C56  0.22uF  [CAP_0201]
C57  0.22uF  [CAP_0201]
C58  0.22uF  [CAP_0201]
C59  0.22uF  [CAP_0201]
C60  0.1uF  [CAP_0402]
C61  0.22uF  [CAP_0201]
C62  0.22uF  [CAP_0201]
C63  10uF  [CAP_0603]
C64  0.1uF  [CAP_0402]
C65  0.1uF  [CAP_0402]
C66  10uF  [CAP_0603]
C67  0.1uF  [CAP_0402]
C68  0.1uF  [CAP_0402]
J3  HDR3X1 M .1  [HDR_THVT_1x3_254_838]
J4  HDR3X1 M .1  [HDR_THVT_1x3_254_838]
L3  6.8uH  [IND_SM_DRA73]
L4  6.8uH  [IND_SM_DRA73]
U3  DS320PR421  [RUA0042BA_205X755]
U4  DS320PR421  [RUA0042BA_205X755]
sheet PAGE4
J22  HDR2X1 M .1  [HDR_THVT_1X2_254_871]
J23  HDR5X2 .1X.1  [HDR_THVT_2X5_254_838]
J24  HDR5X2 .1X.1  [HDR_THVT_2X5_254_838]
J25  HDR5X2 .1X.1  [HDR_THVT_2X5_254_838]
J26  HDR5X2 .1X.1  [HDR_THVT_2X5_254_838]
J27  HDR5X2 .1X.1  [HDR_THVT_2X5_254_838]
J28  HDR5X2 .1X.1  [HDR_THVT_2X5_254_838]
J29  HDR5X2 .1X.1  [HDR_THVT_2X5_254_838]
J30  HDR5X2 .1X.1  [HDR_THVT_2X5_254_838]
JMP1  Header 4x2  [HDR_THVT_2X4_254_871]
JMP2  Header 4x2  [HDR_THVT_2X4_254_871]
JMP3  Header 4x2  [HDR_THVT_2X4_254_871]
JMP4  Header 4x2  [HDR_THVT_2X4_254_871]
JMP5  Header 4x2  [HDR_THVT_2X4_254_871]
JMP6  Header 4x2  [HDR_THVT_2X4_254_871]
JMP7  Header 3x1  [hdr_thvt_1x3_254_871]
JMP8  Header 3x1  [hdr_thvt_1x3_254_871]
JMP9  Header 4x2  [HDR_THVT_2X4_254_871]
JMP10  Header 4x2  [HDR_THVT_2X4_254_871]
JMP11  Header 4x2  [HDR_THVT_2X4_254_871]
JMP14  Header 4x2  [HDR_THVT_2X4_254_871]
JMP15  Header 4x2  [HDR_THVT_2X4_254_871]
JMP16  Header 4x2  [HDR_THVT_2X4_254_871]
R1  1K  [RES_0402]
R2  8.25K  [RES_0402]
R3  24.9K  [RES_0402]
R4  75K  [RES_0402]
R5  1K  [RES_0402]
R6  8.25K  [RES_0402]
R7  24.9K  [RES_0402]
R8  75K  [RES_0402]
R9  1K  [RES_0402]
R10  8.25K  [RES_0402]
R11  24.9K  [RES_0402]
R12  75K  [RES_0402]
R13  1K  [RES_0402]
R14  8.25K  [RES_0402]
R15  24.9K  [RES_0402]
R16  75K  [RES_0402]
R17  1K  [RES_0402]
R18  8.25K  [RES_0402]
R19  24.9K  [RES_0402]
R20  75K  [RES_0402]
R21  1K  [RES_0402]
R22  8.25K  [RES_0402]
R23  24.9K  [RES_0402]
R24  75K  [RES_0402]
R25  1K  [RES_0402]
R26  8.25K  [RES_0402]
R27  24.9K  [RES_0402]
R28  75K  [RES_0402]
R29  1K  [RES_0402]
R30  8.25K  [RES_0402]
R31  1K  [RES_0402]
R32  1K  [RES_0402]
R33  1K  [RES_0402]
R34  1K  [RES_0402]
R35  1K  [RES_0402]
R36  1K  [RES_0402]
R37  1K  [RES_0402]
R38  1K  [RES_0402]
R39  24.9K  [RES_0402]
R40  75K  [RES_0402]
R41  1K  [RES_0402]
R42  8.25K  [RES_0402]
R43  24.9K  [RES_0402]
R44  75K  [RES_0402]
R45  1K  [RES_0402]
R46  8.25K  [RES_0402]
R47  24.9K  [RES_0402]
R48  75K  [RES_0402]
R49  1K  [RES_0402]
R50  8.25K  [RES_0402]
R51  24.9K  [RES_0402]
R52  75K  [RES_0402]
R53  1K  [RES_0402]
R62  8.25K  [RES_0402]
R63  24.9K  [RES_0402]
R64  75K  [RES_0402]
R65  1K  [RES_0402]
R66  8.25K  [RES_0402]
R67  24.9K  [RES_0402]
R68  75K  [RES_0402]
R69  1K  [RES_0402]
R70  8.25K  [RES_0402]
R71  24.9K  [RES_0402]
R72  75K  [RES_0402]
R73  1K  [RES_0402]
R74  8.25K  [RES_0402]
R75  24.9K  [RES_0402]
R76  75K  [RES_0402]
R133  1K  [RES_0402]
R134  8.25K  [RES_0402]
R135  24.9K  [RES_0402]
R136  75K  [RES_0402]
R137  1K  [RES_0402]
R138  8.25K  [RES_0402]
R139  24.9K  [RES_0402]
R140  75K  [RES_0402]
R141  1K  [RES_0402]
R142  8.25K  [RES_0402]
R143  24.9K  [RES_0402]
R144  75K  [RES_0402]
R145  1K  [RES_0402]
R146  8.25K  [RES_0402]
R147  24.9K  [RES_0402]
R148  75K  [RES_0402]
R149  1K  [RES_0402]
R150  8.25K  [RES_0402]
R151  24.9K  [RES_0402]
R152  75K  [RES_0402]
sheet PAGE5
J5  HDR3X2 .1X.1  [HDR_THVT_2X3_254_871]
J6  HDR3X2 .1X.1  [HDR_THVT_2X3_254_871]
J7  HDR3X2 .1X.1  [HDR_THVT_2X3_254_871]
J8  HDR3X2 .1X.1  [HDR_THVT_2X3_254_871]
J9  HDR3X2 .1X.1  [HDR_THVT_2X3_254_871]
JMP17  Header 3x1  [hdr_thvt_1x3_254_871]
P4  Header 5x2 0.1" Shroud RA thru-hole  [CON_SHRD_THRT_30310-5002HB]
R77  1K  [RES_0402]
R78  1K  [RES_0402]
R79  4.7K  [RES_0402]
R80  4.7K  [RES_0402]
U5  TMUX1133PWR  [PW0016AB]
sheet PAGE6
C69  0.1uF  [CAP_0402]
C70  100uF  [TANT_3216-18]
C71  47uF  [CAP_0805]
C72  10uF  [CAP_0603]
C73  4.7uF  [CAP_0402]
C74  1uF  [CAP_0402]
C75  0.47uF  [CAP_0402]
C76  0.1uF  [CAP_0402]
C78  1uF  [CAP_0402]
C79  4.7uF  [CAP_0402]
C80  22uF  [CAP_0603]
C81  100uF  [TANT_3216-18]
C82  22uF  [CAP_0603]
C104  10uF  [CAP_0603]
C105  1uF  [CAP_0402]
D1  LED Green 0805  [LED_0805]
D2  LED Green 0805  [LED_0805]
J10  HDR2X1 M .1  [HDR_THVT_1X2_254_871]
J11  HDR2X1 M .1  [HDR_THVT_1X2_254_871]
L5  6.8uH  [IND_SM_DRA73]
R81  165K  [RES_0402]
R82  121K  [RES_0402]
R83  330  [RES_0402]
R84  37.4K  [RES_0402]
R85  100K  [RES_0402]
R86  100K  [RES_0402]
R87  100K  [RES_0402]
R88  165K  [RES_0402]
R89  42.2K  [RES_0402]
R90  105K  [RES_0402]
R91  205K  [RES_0402]
R92  5.76K  [RES_0402]
R93  10K  [RES_0402]
R94  330  [RES_0402]
R131  10K  [RES_0402]
R132  10K  [RES_0402]
U6  TPS548B22RVFT  [RVF0040BA_330x530]
U7  SN74LVC125A_PW_14  [PW0014AA]
sheet PAGE7
C83  1pF  [CAP_0402]
C84  1pF  [CAP_0402]
C85  1pF  [CAP_0402]
C86  1pF  [CAP_0402]
C87  1pF  [CAP_0402]
C88  1pF  [CAP_0402]
C89  1pF  [CAP_0402]
C90  1pF  [CAP_0402]
C91  1pF  [CAP_0402]
C92  1pF  [CAP_0402]
C93  1pF  [CAP_0402]
J17  HDR3X2 .1X.1  [HDR_THVT_2X3_254_871]
J18  HDR3X2 .1X.1  [HDR_THVT_2X3_254_871]
J19  HDR3X2 .1X.1  [HDR_THVT_2X3_254_871]
J20  HDR3X2 .1X.1  [HDR_THVT_2X3_254_871]
J21  HDR3X2 .1X.1  [HDR_THVT_2X3_254_871]
P5  PCIe Gen 5 Edge Connector  [CON_EDGE_164_100_Gen5]
R95  43  [RES_0402]
R96  43  [RES_0402]
R97  43  [RES_0402]
R98  43  [RES_0402]
R99  43  [RES_0402]
R100  43  [RES_0402]
R101  43  [RES_0402]
R102  43  [RES_0402]
R103  43  [RES_0402]
R104  43  [RES_0402]
R105  43  [RES_0402]
sheet PAGE8
C94  0.1uF  [CAP_0402]
C95  0.1uF  [CAP_0402]
C96  0.1uF  [CAP_0402]
C97  0.1uF  [CAP_0402]
C98  0.1uF  [CAP_0402]
C99  0.1uF  [CAP_0402]
C100  0.1uF  [CAP_0402]
C101  0.1uF  [CAP_0402]
C102  1uF  [CAP_0402]
C103  10uF  [CAP_0603]
J12  SMP  [CON_SMVT_19S101-40ML5_R04350]
J13  SMP  [CON_SMVT_19S101-40ML5_R04350]
J14  SMP  [CON_SMVT_19S101-40ML5_R04350]
JMP18  Header 3x1  [hdr_thvt_1x3_254_871]
JMP19  Header 3x1  [hdr_thvt_1x3_254_871]
JMP20  Header 3x1  [hdr_thvt_1x3_254_871]
L6  6.8uH  [IND_SM_DRA73]
R106  49.9  [RES_0402]
R107  33  [RES_0402]
R108  33  [RES_0402]
R109  33  [RES_0402]
R110  33  [RES_0402]
R115  49.9  [RES_0402]
R116  49.9  [RES_0402]
R117  49.9  [RES_0402]
R118  100 DNI  [RES_0402]
R119  100 DNI  [RES_0402]
R120  1K  [RES_0402]
U8  LMK00334RTVR  [RTV0032BA_310x310]
sheet PAGE9
J15  10146070-113Y0LF  [CON_SMVT_10146070-113Y0LF]
R121  1  [RES_0402]
R122  1  [RES_0402]
R123  1  [RES_0402]
R124  1  [RES_0402]
R125  1  [RES_0402]
sheet PAGE10
J16  10146070-113Y0LF  [CON_SMVT_10146070-113Y0LF]
R126  1  [RES_0402]
R127  1  [RES_0402]
R128  1  [RES_0402]
R129  1  [RES_0402]
R130  1  [RES_0402]
sheet PAGE11
LB1  THD-47-478-10  [rectangle]
PCB1  HSDC110A  [n/a]
SHNT1  QPC02SXGN-RC  [0.1]
SHNT2  QPC02SXGN-RC  [0.1]
SHNT3  QPC02SXGN-RC  [0.1]
SHNT4  QPC02SXGN-RC  [0.1]
SHNT5  QPC02SXGN-RC  [0.1]
SHNT6  QPC02SXGN-RC  [0.1]
SHNT7  QPC02SXGN-RC  [0.1]
SHNT8  QPC02SXGN-RC  [0.1]
SHNT9  QPC02SXGN-RC  [0.1]
SHNT10  QPC02SXGN-RC  [0.1]
SHNT11  QPC02SXGN-RC  [0.1]
SHNT12  QPC02SXGN-RC  [0.1]
SHNT13  QPC02SXGN-RC  [0.1]
SHNT14  QPC02SXGN-RC  [0.1]
SHNT15  QPC02SXGN-RC  [0.1]
SHNT16  QPC02SXGN-RC  [0.1]
SHNT17  QPC02SXGN-RC  [0.1]
SHNT18  QPC02SXGN-RC  [0.1]
SHNT19  QPC02SXGN-RC  [0.1]
SHNT20  QPC02SXGN-RC  [0.1]
SHNT21  QPC02SXGN-RC  [0.1]
SHNT22  QPC02SXGN-RC  [0.1]
SHNT23  QPC02SXGN-RC  [0.1]
SHNT24  QPC02SXGN-RC  [0.1]
SHNT25  QPC02SXGN-RC  [0.1]
SHNT26  QPC02SXGN-RC  [0.1]

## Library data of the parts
C1 C2 C22 C32 C38 C39 C41-C43 C50 C53 C60 C64 C65 C67-C69 C76 C94-C101 = GRM155R71A104KA01J
C3-C21 C23-C31 C33-C36 C44-C49 C51 C52 C54-C59 C61 C62 = C0603X5R0J224K030BB
C37 C40 C63 C66 C103 = GRM188R60J106ME47D
J1-J4 = HDR3X1_M_.1
L1-L6 = L_8A: Imax: 2.62A; Manuf PN: DRA73-6R8-R; Manufacturer: Eaton; Mfr_Name: Eaton; Mfr_Part_Number: DRA73-6R8-R
U1 U2 = DS320PR412_3
U3 U4 = DS320PR421_1
J10 J11 J22 = HDR2X1_M_.1
J23-J30 = HDR5X2_M_.1X.1
JMP1-JMP6 JMP9-JMP11 JMP14-JMP16 = Header_4x2: Manuf PN: 103322-4; Manufacturer: AMP
JMP7 JMP8 JMP17-JMP20 = Header_3x1: Manuf PN: 103321-3; Manufacturer: AMP
R1 R5 R9 R13 R17 R21 R25 R29 R41 R45 R49 R53 R65 R69 R73 R133 R137 R141 R145 R149 = ERJ-2GEJ102X_0
R2 R6 R10 R14 R18 R22 R26 R30 R42 R46 R50 R62 R66 R70 R74 R134 R138 R142 R146 R150 = ERJ-2RKF8251X_0
R3 R7 R11 R15 R19 R23 R27 R39 R43 R47 R51 R63 R67 R71 R75 R135 R139 R143 R147 R151 = ERA-2AEB2492X_0
R4 R8 R12 R16 R20 R24 R28 R40 R44 R48 R52 R64 R68 R72 R76 R136 R140 R144 R148 R152 = ERA-2AED753X_0
R31-R38 R77 R78 R120 = ERJ-2GEJ102X_1
J5-J9 J17-J21 = HDR3X2_M_.1X.1
P4 = CONN_PCB_5x2-S: Digi-Key Part Number: 3M15452-ND; Manuf PN: 30310-5002HB; Manufacturer: 3M; Manufacturer Part Number: 20210-5002HB; Manufacturer's Part Number: 30310-5002HB
R79 R80 = ERJ-2GEJ472X_0
U5 = TMUX1133PWR: Manufacturer: Texas Instruments
C70 C81 = T520A107M006ATE070
C71 = JMK212BJ476MG-T
C72 C104 = GRM188R61A106KE69D
C73 C79 = GRM155R60J475ME47D
C74 C78 C102 C105 = CC0402KRX5R6BB105
C75 = GRM155R60J474KE19D
C80 C82 = C0603C224K8NACTU: Manufacturer: Murata; Manufacturer PN: GRM188C80G226MEA0D; Manufacturer's Part Number: GRM188C80G226MEA0D; Manufacturer_Part_Number: GRM188C80G226MEA0D; Vendor: Murata
D1 D2 = LED_Green_0805_0
R81 = ERJ-2RKF1653X_0
R82 = RC0402FR-07121KL_0
R83 R94 = ERA-2AEB331X_0
R84 = ERJ-2RKF3742X_0
R85-R87 = ERJ-2GEJ104X_0
R88 = ERJ-2RKF1653X_1
R89 = ERJ-2RKF4222X_0
R90 = ERJ-2RKF1053X_0
R91 = ERJ-2RKF2053X_0
R92 = ERJ-2RKF5761X_0
R93 R131 R132 = ERA-2AED103X_0
U6 = TPS548B22RVFT_1
U7 = SN74LVC125AQPWRQ1
C83-C93 = GRM1555C1H1R0CA01D
P5 = PCIe_Gen_5_Edge_Connector_2
R95-R105 = r0402: Manuf PN: ERA-2AKD430X; Manufacturer: Panasonic
J12-J14 = SMP_0: Manuf PN: 19S101-40ML5; SILKTEXT1: HS pair 3
R106 R115-R117 = ERJ-2RKF49R9X_0
R107-R110 = ERA-2AKD330X_0
R118 R119 = ERA-2AED101X_0
U8 = LMK00334RTVR_0
J15 J16 = PCIe_GEN_5_x16_SMT_CEM_1
R121-R130 = RC0402FR-071RL_0
LB1 = Label: Manuf PN: THT-14-423-10; Manufacturer: Brady; Manufacturer's Part Number: THT-14-423-10
PCB1 = PCB: Manufacturer: Any; Manufacturer Part Number: HSDC069; Manufacturer's Part Number: HSDC069
SHNT1-SHNT26 = Shunt: Manufacturer: Sullins Connector Solutions

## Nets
+3.3V: C70.1 C71.2 C72.2 C73.2 C74.2 C75.2 C76.2 C105.2 J10.1 JMP7.1 JMP8.1 L1.1 L2.1 L3.1 L4.1 L5.1 L6.2 R77.2 R79.1 R80.1 R93.2 R120.1 R131.1 U5.16(VDD) U6.40(VOSNS) U7.5(2A) U7.14(VCC)
+3.3VA: J15.B10(3.3_Vaux) J16.B10(3.3_Vaux) P5.B10(3.3_Vaux)
+3V: J1.1 J2.1 J3.1 J4.1 J15.A9(3.3V1) J15.A10(3.3V2) J15.B8(3.3V3) J16.A9(3.3V1) J16.A10(3.3V2) J16.B8(3.3V3) P5.A9(3.3V3) P5.A10(3.3V2) P5.B8(3.3V1)
+12V: C78.2 C79.2 C80.2 C81.1 C82.2 J11.1 J15.A2(12V1) J15.A3(12V2) J15.B1(12V5) J15.B2(12V4) J15.B3(12V3) J16.A2(12V1) J16.A3(12V2) J16.B1(12V5) J16.B2(12V4) J16.B3(12V3) P5.A2(12V5) P5.A3(12V4) P5.B1(12V1) P5.B2(12V2) P5.B3(12V3) R81.1 U6.21(PVIN) U6.22(PVIN_1) U6.23(PVIN_2) U6.24(PVIN_3) U6.25(PVIN_4) U6.28(VDD)
GND: C1.1 C2.1 C22.1 C32.1 C37.1 C38.1 C39.1 C40.1 C41.1 C42.1 C43.2 C50.2 C53.2 C60.2 C63.1 C64.1 C65.1 C66.1 C67.1 C68.1 C70.2 C71.1 C72.1 C73.1 C74.1 C75.1 C76.1 C78.1 C79.1 C80.1 C81.2 C82.1 C94.1 C95.1 C96.1 C97.1 C98.1 C99.1 C100.1 C101.1 C102.1 C103.1 C104.1 J10.2 J11.2 J12.2 J12.3 J12.4 J12.5 J12.6 J12.7 J12.8 J12.9 J12.10 J13.2 J13.3 J13.4 J13.5 J13.6 J13.7 J13.8 J13.9 J13.10 J14.2 J14.3 J14.4 J14.5 J14.6 J14.7 J14.8 J14.9 J14.10 J15.A4(GND1) J15.A12(GND2) J15.A15(GND3) J15.A18(GND4) J15.A20(GND5) J15.A23(GND6) J15.A24(GND7) J15.A27(GND8) J15.A28(GND9) J15.A31(GND10) J15.A34(GND11) J15.A37(GND12) J15.A38(GND13) J15.A41(GND14) J15.A42(GND15) J15.A45(GND16) J15.A46(GND17) J15.A49(GND18) J15.A51(GND19) J15.A54(GND20) J15.A55(GND21) J15.A58(GND22) J15.A59(GND23) J15.A62(GND24) J15.A63(GND25) J15.A66(GND26) J15.A67(GND27) J15.A70(GND28) J15.A71(GND29) J15.A74(GND30) J15.A75(GND31) J15.A78(GND32) J15.A79(GND33) J15.A82(GND34) J15.B4(GND68) J15.B7(GND67) J15.B13(GND66) J15.B16(GND65) J15.B18(GND64) J15.B21(GND63) J15.B22(GND62) J15.B25(GND61) J15.B26(GND60) J15.B29(GND59) J15.B32(GND58) J15.B35(GND57) J15.B36(GND56) J15.B39(GND55) J15.B40(GND54) J15.B43(GND53) J15.B44(GND52) J15.B47(GND51) J15.B49(GND50) J15.B52(GND49) J15.B53(GND48) J15.B56(GND47) J15.B57(GND46) J15.B60(GND45) J15.B61(GND44) J15.B64(GND43) J15.B65(GND42) J15.B68(GND41) J15.B69(GND40) J15.B72(GND39) J15.B73(GND38) J15.B76(GND37) J15.B77(GND36) J15.B80(GND35) J16.A4(GND1) J16.A12(GND2) J16.A15(GND3) J16.A18(GND4) J16.A20(GND5) J16.A23(GND6) J16.A24(GND7) J16.A27(GND8) J16.A28(GND9) J16.A31(GND10) J16.A34(GND11) J16.A37(GND12) J16.A38(GND13) J16.A41(GND14) J16.A42(GND15) J16.A45(GND16) J16.A46(GND17) J16.A49(GND18) J16.A51(GND19) J16.A54(GND20) J16.A55(GND21) J16.A58(GND22) J16.A59(GND23) J16.A62(GND24) J16.A63(GND25) J16.A66(GND26) J16.A67(GND27) J16.A70(GND28) J16.A71(GND29) J16.A74(GND30) J16.A75(GND31) J16.A78(GND32) J16.A79(GND33) J16.A82(GND34) J16.B4(GND68) J16.B7(GND67) J16.B13(GND66) J16.B16(GND65) J16.B18(GND64) J16.B21(GND63) J16.B22(GND62) J16.B25(GND61) J16.B26(GND60) J16.B29(GND59) J16.B32(GND58) J16.B35(GND57) J16.B36(GND56) J16.B39(GND55) J16.B40(GND54) J16.B43(GND53) J16.B44(GND52) J16.B47(GND51) J16.B49(GND50) J16.B52(GND49) J16.B53(GND48) J16.B56(GND47) J16.B57(GND46) J16.B60(GND45) J16.B61(GND44) J16.B64(GND43) J16.B65(GND42) J16.B68(GND41) J16.B69(GND40) J16.B72(GND39) J16.B73(GND38) J16.B76(GND37) J16.B77(GND36) J16.B80(GND35) J18.6 J19.6 J20.6 J21.6 JMP7.3 JMP8.3 JMP18.3 JMP19.3 JMP20.3 P5.A4(GND) P5.A12(GND67) P5.A15(GND66) P5.A18(GND65) P5.A20(GND64) P5.A23(GND63) P5.A24(GND62) P5.A27(GND61) P5.A28(GND60) P5.A31(GND59) P5.A34(GND58) P5.A37(GND57) P5.A38(GND56) P5.A41(GND55) P5.A42(GND54) P5.A45(GND53) P5.A46(GND52) P5.A49(GND51) P5.A51(GND50) P5.A54(GND49) P5.A55(GND48) P5.A58(GND47) P5.A59(GND46) P5.A62(GND45) P5.A63(GND44) P5.A66(GND43) P5.A67(GND42) P5.A70(GND41) P5.A71(GND40) P5.A74(GND39) P5.A75(GND38) P5.A78(GND37) P5.A79(GND36) P5.A82(GND35) P5.B4(GND1) P5.B7(GND2) P5.B13(GND3) P5.B16(GND4) P5.B18(GND5) P5.B21(GND6) P5.B22(GND7) P5.B25(GND8) P5.B26(GND9) P5.B29(GND10) P5.B32(GND11) P5.B35(GND12) P5.B36(GND13) P5.B39(GND14) P5.B40(GND15) P5.B43(GND16) P5.B44(GND17) P5.B47(GND18) P5.B49(GND19) P5.B52(GND20) P5.B53(GND21) P5.B56(GND22) P5.B57(GND23) P5.B60(GND24) P5.B61(GND25) P5.B64(GND26) P5.B65(GND27) P5.B68(GND28) P5.B69(GND29) P5.B72(GND30) P5.B73(GND31) P5.B76(GND32) P5.B77(GND33) P5.B80(GND34) R1.1 R2.1 R3.2 R4.1 R5.1 R6.1 R7.2 R8.1 R9.1 R10.1 R11.2 R12.1 R13.1 R14.1 R15.2 R16.1 R17.1 R18.1 R19.2 R20.1 R21.1 R22.1 R23.2 R24.1 R25.1 R26.1 R27.2 R28.1 R29.1 R30.1 R39.2 R40.1 R41.1 R42.1 R43.2 R44.1 R45.1 R46.1 R47.2 R48.1 R49.1 R50.1 R51.2 R52.1 R53.1 R62.1 R63.2 R64.1 R65.1 R66.1 R67.2 R68.1 R69.1 R70.1 R71.2 R72.1 R73.1 R74.1 R75.2 R76.1 R78.2 R82.2 R83.1 R84.1 R88.2 R89.2 R91.1 R92.1 R94.1 R95.2 R96.2 R97.2 R98.2 R99.2 R100.2 R101.2 R102.2 R103.2 R104.2 R105.2 R106.2 R115.2 R116.2 R117.2 R132.2 R133.1 R134.1 R135.2 R136.1 R137.1 R138.1 R139.2 R140.1 R141.1 R142.1 R143.2 R144.1 R145.1 R146.1 R147.2 R148.1 R149.1 R150.1 R151.2 R152.1 U1.6(GND) U1.9(GND) U1.16(GND) U1.21(GND) U1.30(GND) U1.39(GND) U1.43(PAD) U2.6(GND) U2.9(GND) U2.16(GND) U2.21(GND) U2.30(GND) U2.39(GND) U2.43(PAD) U3.6(GND) U3.9(GND) U3.16(GND) U3.21(GND) U3.30(GND) U3.39(GND) U3.43(PAD) U4.6(GND) U4.9(GND) U4.16(GND) U4.21(GND) U4.30(GND) U4.39(GND) U4.43(PAD) U5.4(D3) U5.6(EN_N) U5.7(VSS) U5.8(GND) U6.13(PGND) U6.14(PGND_1) U6.15(PGND_2) U6.16(PGND_3) U6.17(PGND_4) U6.18(PGND_5) U6.19(PGND_6) U6.20(PGND_7) U6.29(DRGND) U6.30(AGND) U6.38(RSN) U6.41(EPAD) U7.7(GND) U7.12(4A) U7.13(*4OE) U8.1(GND) U8.8(GND_1) U8.16(CLKIN_SEL1) U8.17(GND_2) U8.24(GND_3) U8.33(DAP)
VCC0: C37.2 C38.2 C39.2 J1.2 U1.5(VCC) U1.13(VCC)
VCC1: C40.2 C41.2 C42.2 J2.2 U2.5(VCC) U2.13(VCC)
VCC2: C63.2 C64.2 C65.2 J3.2 U3.5(VCC) U3.13(VCC)
VCC3: C66.2 C67.2 C68.2 J4.2 U4.5(VCC) U4.13(VCC)
BP: C104.2 R85.1 R86.1 R87.1 R90.1 U6.31(BP)
CLKREQ: C83.1 P5.B12(RSVD1) R125.1 R130.1
EQ0_ADDR_0: JMP1.1 JMP1.3 JMP1.5 JMP1.7 U1.40(EQ0/ADDR)
EQ0_ADDR_1: JMP4.1 JMP4.3 JMP4.5 JMP4.7 U2.40(EQ0/ADDR)
EQ0_ADDR_2: JMP9.1 JMP9.3 JMP9.5 JMP9.7 U3.40(EQ0/ADDR)
EQ0_ADDR_3: JMP14.1 JMP14.3 JMP14.5 JMP14.7 U4.40(EQ0/ADDR)
EQ1_0: JMP2.1 JMP2.3 JMP2.5 JMP2.7 U1.20(EQ1)
EQ1_1: JMP5.1 JMP5.3 JMP5.5 JMP5.7 U2.20(EQ1)
EQ1_2: JMP10.1 JMP10.3 JMP10.5 JMP10.7 U3.20(EQ1)
EQ1_3: JMP15.1 JMP15.3 JMP15.5 JMP15.7 U4.20(EQ1)
GAIN_SDA_0: J23.1 J23.3 J23.5 J23.7 J23.9 U1.1(GAIN/SDA)
GAIN_SDA_1: J25.1 J25.3 J25.5 J25.7 J25.9 U2.1(GAIN/SDA)
GAIN_SDA_2: J27.1 J27.3 J27.5 J27.7 J27.9 U3.1(GAIN/SDA)
GAIN_SDA_3: J29.1 J29.3 J29.5 J29.7 J29.9 U4.1(GAIN/SDA)
JTAG1: J5.3 P5.B9(J_TRST#)
JTAG1_A: J5.1 J15.B9(J_TRST#)
JTAG1_B: J5.5 J16.B9(J_TRST#)
JTAG2: J6.3 P5.A5(J_TCK)
JTAG2_A: J6.1 J15.A5(J_TCK)
JTAG2_B: J6.5 J16.A5(J_TCK)
JTAG3: J7.3 P5.A6(J_TDI)
JTAG3_A: J7.1 J15.A6(J_TDI)
JTAG3_B: J7.5 J16.A6(J_TDI)
JTAG4: J8.3 P5.A7(J_TDO)
JTAG4_A: J8.1 J15.A7(J_TDO)
JTAG4_B: J8.5 J16.A7(J_TDO)
JTAG5: J9.3 P5.A8(J_TMS)
JTAG5_A: J9.1 J15.A8(J_TMS)
JTAG5_B: J9.5 J16.A8(J_TMS)
MODE: R87.2 R89.1 U6.34(MODE)
MODE_0: JMP3.1 JMP3.3 JMP3.5 JMP3.7 U1.41(MODE)
MODE_1: JMP6.1 JMP6.3 JMP6.5 JMP6.7 U2.41(MODE)
MODE_2: JMP11.1 JMP11.3 JMP11.5 JMP11.7 U3.41(MODE)
MODE_3: JMP16.1 JMP16.3 JMP16.5 JMP16.7 U4.41(MODE)
PD_0: R35.2 U1.18(PD)
PD_1: R36.2 U2.18(PD)
PD_2: R37.2 U3.18(PD)
PD_3: R38.2 U4.18(PD)
PER0_N: J16.A17(TXn0) P5.A17(TXn0)
PER0_N_A: J15.A17(TXn0) U3.37(RXA0N)
PER0_P: J16.A16(TXp0) P5.A16(TXp0)
PER0_P_A: J15.A16(TXp0) U3.38(RXA0P)
PER1_N: J16.A22(TXn1) P5.A22(TXn1)
PER1_N_A: J15.A22(TXn1) U3.33(RXA1N)
PER1_P: J16.A21(TXp1) P5.A21(TXp1)
PER1_P_A: J15.A21(TXp1) U3.34(RXA1P)
PER2_N: J16.A26(TXn2) P5.A26(TXn2)
PER2_N_A: J15.A26(TXn2) U3.28(RXA2N)
PER2_P: J16.A25(TXp2) P5.A25(TXp2)
PER2_P_A: J15.A25(TXp2) U3.29(RXA2P)
PER3_N: J16.A30(TXn3) P5.A30(TXn3)
PER3_N_A: J15.A30(TXn3) U3.24(RXA3N)
PER3_P: J16.A29(TXp3) P5.A29(TXp3)
PER3_P_A: J15.A29(TXp3) U3.25(RXA3P)
PER4_N: J16.A36(TXn4) P5.A36(TXn4)
PER4_N_A: J15.A36(TXn4) U4.37(RXA0N)
PER4_P: J16.A35(TXp4) P5.A35(TXp4)
PER4_P_A: J15.A35(TXp4) U4.38(RXA0P)
PER5_N: J16.A40(TXn5) P5.A40(TXn5)
PER5_N_A: J15.A40(TXn5) U4.33(RXA1N)
PER5_P: J16.A39(TXp5) P5.A39(TXp5)
PER5_P_A: J15.A39(TXp5) U4.34(RXA1P)
PER6_N: J16.A44(TXn6) P5.A44(TXn6)
PER6_N_A: J15.A44(TXn6) U4.28(RXA2N)
PER6_P: J16.A43(TXp6) P5.A43(TXp6)
PER6_P_A: J15.A43(TXp6) U4.29(RXA2P)
PER7_N: J16.A48(TXn7) P5.A48(TXn7)
PER7_N_A: J15.A48(TXn7) U4.24(RXA3N)
PER7_P: J16.A47(TXp7) P5.A47(TXp7)
PER7_P_A: J15.A47(TXp7) U4.25(RXA3P)
PER8_N: C45.1 P5.A53(TXn8)
PER8_N_B: J16.A53(TXn8) U3.35(RXB0N)
PER8_P: C44.1 P5.A52(TXp8)
PER8_P_B: J16.A52(TXp8) U3.36(RXB0P)
PER9_N: C47.1 P5.A57(TXn9)
PER9_N_B: J16.A57(TXn9) U3.31(RXB1N)
PER9_P: C46.1 P5.A56(TXp9)
PER9_P_B: J16.A56(TXp9) U3.32(RXB1P)
PER10_N: C49.1 P5.A61(TXn10)
PER10_N_B: J16.A61(TXn10) U3.26(RXB2N)
PER10_P: C48.1 P5.A60(TXp10)
PER10_P_B: J16.A60(TXp10) U3.27(RXB2P)
PER11_N: C52.1 P5.A65(TXn11)
PER11_N_B: J16.A65(TXn11) U3.22(RXB3N)
PER11_P: C51.1 P5.A64(TXp11)
PER11_P_B: J16.A64(TXp11) U3.23(RX3BP)
PER12_N: C55.1 P5.A69(TXn12)
PER12_N_B: J16.A69(TXn12) U4.35(RXB0N)
PER12_P: C54.1 P5.A68(TXp12)
PER12_P_B: J16.A68(TXp12) U4.36(RXB0P)
PER13_N: C57.1 P5.A73(TXn13)
PER13_N_B: J16.A73(TXn13) U4.31(RXB1N)
PER13_P: C56.1 P5.A72(TXp13)
PER13_P_B: J16.A72(TXp13) U4.32(RXB1P)
PER14_N: C59.1 P5.A77(TXn14)
PER14_N_B: J16.A77(TXn14) U4.26(RXB2N)
PER14_P: C58.1 P5.A76(TXp14)
PER14_P_B: J16.A76(TXp14) U4.27(RXB2P)
PER15_N: C62.1 P5.A81(TXn15)
PER15_N_B: J16.A81(TXn15) U4.22(RXB3N)
PER15_P: C61.1 P5.A80(TXp15)
PER15_P_B: J16.A80(TXp15) U4.23(RX3BP)
PERST#: J17.3 P5.A11(PERST#) U7.10(*3OE)
PERST#_A: J17.1 R121.2
PERST#_B: J17.5 R128.2
PERST_INV: J22.2 U7.8(3Y)
PET0_N: J16.B15(RXn0) P5.B15(RXn0)
PET0_N_A: C4.2 J15.B15(RXn0)
PET0_P: J16.B14(RXp0) P5.B14(RXp0)
PET0_P_A: C3.2 J15.B14(RXp0)
PET1_N: J16.B20(RXn1) P5.B20(RXn1)
PET1_N_A: C8.2 J15.B20(RXn1)
PET1_P: J16.B19(RXp1) P5.B19(RXp1)
PET1_P_A: C7.2 J15.B19(RXp1)
PET2_N: J16.B24(RXn2) P5.B24(RXn2)
PET2_N_A: C12.2 J15.B24(RXn2)
PET2_P: J16.B23(RXp2) P5.B23(RXp2)
PET2_P_A: C11.2 J15.B23(RXp2)
PET3_N: J16.B28(RXn3) P5.B28(RXn3)
PET3_N_A: C16.2 J15.B28(RXn3)
PET3_P: J16.B27(RXp3) P5.B27(RXp3)
PET3_P_A: C15.2 J15.B27(RXp3)
PET4_N: J16.B34(RXn4) P5.B34(RXn4)
PET4_N_A: C20.2 J15.B34(RXn4)
PET4_P: J16.B33(RXp4) P5.B33(RXp4)
PET4_P_A: C19.2 J15.B33(RXp4)
PET5_N: J16.B38(RXn5) P5.B38(RXn5)
PET5_N_A: C25.2 J15.B38(RXn5)
PET5_P: J16.B37(RXp5) P5.B37(RXp5)
PET5_P_A: C24.2 J15.B37(RXp5)
PET6_N: J16.B42(RXn6) P5.B42(RXn6)
PET6_N_A: C29.2 J15.B42(RXn6)
PET6_P: J16.B41(RXp6) P5.B41(RXp6)
PET6_P_A: C28.2 J15.B41(RXp6)
PET7_N: J16.B46(RXn7) P5.B46(RXn7)
PET7_N_A: C34.2 J15.B46(RXn7)
PET7_P: J16.B45(RXp7) P5.B45(RXp7)
PET7_P_A: C33.2 J15.B45(RXp7)
PET8_N: P5.B51(RXn8) U1.4(RX0N)
PET8_N_B: C6.2 J16.B51(RXn8)
PET8_P: P5.B50(RXp8) U1.3(RX0P)
PET8_P_B: C5.2 J16.B50(RXp8)
PET9_N: P5.B55(RXn9) U1.8(RX1N)
PET9_N_B: C10.2 J16.B55(RXn9)
PET9_P: P5.B54(RXp9) U1.7(RX1P)
PET9_P_B: C9.2 J16.B54(RXp9)
PET10_N: P5.B59(RXn10) U1.11(RX2N)
PET10_N_B: C14.2 J16.B59(RXn10)
PET10_P: P5.B58(RXp10) U1.10(RX2P)
PET10_P_B: C13.2 J16.B58(RXp10)
PET11_N: P5.B63(RXn11) U1.15(RX3N)
PET11_N_B: C18.2 J16.B63(RXn11)
PET11_P: P5.B62(RXp11) U1.14(RX3P)
PET11_P_B: C17.2 J16.B62(RXp11)
PET12_N: P5.B67(RXn12) U2.4(RX0N)
PET12_N_B: C23.2 J16.B67(RXn12)
PET12_P: P5.B66(RXp12) U2.3(RX0P)
PET12_P_B: C21.2 J16.B66(RXp12)
PET13_N: P5.B71(RXn13) U2.8(RX1N)
PET13_N_B: C27.2 J16.B71(RXn13)
PET13_P: P5.B70(RXp13) U2.7(RX1P)
PET13_P_B: C26.2 J16.B70(RXp13)
PET14_N: P5.B75(RXn14) U2.11(RX2N)
PET14_N_B: C31.2 J16.B75(RXn14)
PET14_P: P5.B74(RXp14) U2.10(RX2P)
PET14_P_B: C30.2 J16.B74(RXp14)
PET15_N: P5.B79(RXn15) U2.15(RX3N)
PET15_N_B: C36.2 J16.B79(RXn15)
PET15_P: P5.B78(RXp15) U2.14(RX3P)
PET15_P_B: C35.2 J16.B78(RXp15)
PGOOD: R90.2 U6.35(PGOOD) U7.2(1A)
PRSNT1: J15.A1(PRSNT1#) J16.A1(PRSNT1#) P5.A1(PRSNT1#)
PRSNT2_1: C90.1 J18.1 J18.3 J18.5 P5.B17(RSVD2)
PRSNT2_1_A: J15.B17(RSVD9) J18.2
PRSNT2_1_B: J16.B17(RSVD9) J18.4
PRSNT2_2: C91.1 J19.1 J19.3 J19.5 P5.B31(RSVD4)
PRSNT2_2_A: J15.B31(RSVD7) J19.2
PRSNT2_2_B: J16.B31(RSVD7) J19.4
PRSNT2_3: C92.1 J20.1 J20.3 J20.5 P5.B48(RSVD5)
PRSNT2_3_A: J15.B48(RSVD6) J20.2
PRSNT2_3_B: J16.B48(RSVD6) J20.4
PRSNT2_4: C93.1 J21.1 J21.3 J21.5 P5.B81(PRSNT2#)
PRSNT2_4_A: J15.B81(PRSNT2#) J21.2
PRSNT2_4_B: J16.B81(PRSNT2#) J21.4
REFCLK_N: P5.A14(REFCLK-) R119.2 U8.15(CLKIN0_N)
REFCLK_P: P5.A13(REFCLK+) R119.1 U8.14(CLKIN0)
REFCLKA_N: J15.A14(REFCLK-) R108.1 R115.1
REFCLKA_P: J15.A13(REFCLK+) R106.1 R107.1
REFCLKB_N: J16.A14(REFCLK-) R110.1 R117.1
REFCLKB_P: J16.A13(REFCLK+) R109.1 R116.1
RSV2: J15.B30(RSVD8) J16.B30(RSVD8)
RSVD: C84.1 J15.B82(RSVD5) J16.B82(RSVD5) P5.B82(RSVD6)
RSVD1: C85.1 J15.A19(RSVD1) J16.A19(RSVD1) P5.A19(RSVD9)
RSVD2: C86.1 P5.B30(RSVD3)
RSVD3: C87.1 J15.A32(RSVD2) J16.A32(RSVD2) P5.A32(RSVD8)
RSVD4: C88.1 J15.A33(RSVD3) J16.A33(RSVD3) P5.A33(RSVD7)
RSVD5: C89.1 J15.A50(RSVD4) J16.A50(RSVD4) P5.A50(RSVD)
RX_DET_SCL_0: J30.1 J30.3 J30.5 J30.7 J30.9 U1.42(RX_DET/SCL)
RX_DET_SCL_1: J24.1 J24.3 J24.5 J24.7 J24.9 U2.42(RX_DET/SCL)
RX_DET_SCL_2: J26.1 J26.3 J26.5 J26.7 J26.9 U3.42(RX_DET/SCL)
RX_DET_SCL_3: J28.1 J28.3 J28.5 J28.7 J28.9 U4.42(RX_DET/SCL)
SCL: J24.10 J26.10 J28.10 J30.10 R79.2 U5.14(D1)
SDA: J23.10 J25.10 J27.10 J29.10 R80.2 U5.15(D2)
SEL_0: R31.2 U1.17(SEL)
SEL_1: R32.2 U2.17(SEL)
SEL_2: R33.2 U3.17(SEL)
SEL_3: R34.2 U4.17(SEL)
SMCLK: P5.B5(SMCLK) R122.1 R126.1
SMDAT: P5.B6(SMDAT) R123.1 R127.1
WAKE: P5.B11(WAKE#) R124.1 R129.1
N16637226: C3.1 U1.38(TXA0P)
N16637238: C19.1 U2.38(TXA0P)
N16637290: C1.2 U1.2(RSVD3)
N16637298: C4.1 U1.37(TXA0N)
N16637306: C22.2 U2.2(RSVD3)
N16637314: C20.1 U2.37(TXA0N)
N16637382: C5.1 U1.36(TXB0P)
N16637394: C21.1 U2.36(TXB0P)
N16637494: C6.1 U1.35(TXB0N)
N16637506: C23.1 U2.35(TXB0N)
N16637572: C7.1 U1.34(TXA1P)
N16637586: C24.1 U2.34(TXA1P)
N16637646: C8.1 U1.33(TXA1N)
N16637662: C25.1 U2.33(TXA1N)
N16637738: C9.1 U1.32(TXB1P)
N16637750: C26.1 U2.32(TXB1P)
N16637818: C10.1 U1.31(TXB1N)
N16637830: C27.1 U2.31(TXB1N)
N16637946: C11.1 U1.29(TXA2P)
N16637958: C28.1 U2.29(TXA2P)
N16638026: C12.1 U1.28(TXA2N)
N16638038: C29.1 U2.28(TXA2N)
N16638090: C2.2 U1.12(RSVD2)
N16638098: C13.1 U1.27(TXB2P)
N16638106: C32.2 U2.12(RSVD2)
N16638114: C30.1 U2.27(TXB2P)
N16638172: C14.1 U1.26(TXB2N)
N16638186: C31.1 U2.26(TXB2N)
N16638286: C15.1 U1.25(TXA3P)
N16638298: C33.1 U2.25(TXA3P)
N16638374: C16.1 U1.24(TXA3N)
N16638386: C34.1 U2.24(TXA3N)
N16638446: C17.1 U1.23(TX3BP)
N16638462: C35.1 U2.23(TX3BP)
N16638538: C18.1 U1.22(TXB3N)
N16638550: C36.1 U2.22(TXB3N)
N16641442: C53.1 U4.2(RSVD3)
N16641458: C43.1 U3.2(RSVD3)
N16641526: C54.2 U4.3(TX0P)
N16641538: C44.2 U3.3(TX0P)
N16641606: C55.2 U4.4(TX0N)
N16641618: C45.2 U3.4(TX0N)
N16641762: C56.2 U4.7(TX1P)
N16641774: C46.2 U3.7(TX1P)
N16641842: C57.2 U4.8(TX1N)
N16641854: C47.2 U3.8(TX1N)
N16641970: C58.2 U4.10(TX2P)
N16641982: C48.2 U3.10(TX2P)
N16642050: C59.2 U4.11(TX2N)
N16642062: C49.2 U3.11(TX2N)
N16642122: C60.1 U4.12(RSVD2)
N16642138: C50.1 U3.12(RSVD2)
N16642238: C61.2 U4.14(TX3P)
N16642250: C51.2 U3.14(TX3P)
N16642318: C62.2 U4.15(TX3N)
N16642330: C52.2 U3.15(TX3N)
N16699752: JMP7.2 R31.1 R32.1 R33.1 R34.1
N16699766: J22.1 JMP8.2 R35.1 R36.1 R37.1 R38.1
N16704207: P4.1 U5.12(S1A)
N16704287: JMP17.1 R77.1
N16704327: P4.9(5) U5.13(S1B)
N16704339: JMP17.2 U5.9(SEL3) U5.10(SEL2) U5.11(SEL1)
N16704387: JMP17.3 R78.1
N16704399: P4.2(6) U5.5(S3A)
N16704407: P4.3(2) U5.2(S2A)
N16704427: P4.6(8) U5.3(S3B)
N16704435: P4.10 U5.1(S2B)
N16704743: J5.2 J5.4 J5.6
N16704833: J9.2 J9.4 J9.6
N16704863: J6.2 J6.4 J6.6
N16704881: J7.2 J7.4 J7.6
N16704899: J8.2 J8.4 J8.6
N16707025: R92.2 R93.1 U6.39(RSP)
N16707333: R86.2 R88.1 U6.33(VSEL)
N16707423: R81.2 R82.1 U6.4(EN_UVLO)
N16707431: R84.2 R85.2 U6.32(FSEL)
N16707493: C69.1 U6.5(BOOT)
N16707501: R91.2 U6.36(ILIM)
N16707563: C69.2 L5.2 U6.8(SW_4) U6.9(SW_3) U6.10(SW_2) U6.11(SW_1) U6.12(SW)
N16708293: C105.1 R132.1 U7.1(*1OE) U7.4(*2OE)
N16708459: D1.1(CATHODE) R83.2
N16708463: D1.2(ANNODE) U7.3(1Y)
N16708493: D2.2(ANNODE) U7.6(2Y)
N16708501: R131.2 U7.9(3A)
N16708621: D2.1(CATHODE) R94.2
N16712321: C83.2 R95.1
N16712467: C84.2 R96.1
N16712565: C85.2 R97.1
N16712707: C86.2 R98.1
N16712843: C87.2 R99.1
N16712983: C88.2 R100.1
N16713127: C89.2 R101.1
N16713267: C90.2 R102.1
N16713407: C91.2 R103.1
N16713543: C92.2 R104.1
N16713689: C93.2 R105.1
N16714257: J17.2 J17.4 J17.6
N16716349: C94.2 C95.2 C96.2 C97.2 C98.2 C99.2 C100.2 C101.2 C102.2 C103.2 JMP18.1 JMP19.1 L6.1 U8.2(VCCOA) U8.5(VCCOA_1) U8.10(VCC) U8.20(VCCOB) U8.23(VCCOB_1) U8.28(VCC_1) U8.30(VCCOC) U8.32(VCC_2)
N16716709: JMP19.2 U8.13(CLKIN_SEL0)
N16716717: JMP18.2 U8.9(CLKOUT_EN_N)
N16716953: R107.2 U8.3(CLKOUTA0)
N16716991: R108.2 U8.4(CLKOUTA0_N)
N16717029: R109.2 U8.6(CLKOUTA1)
N16717077: R110.2 U8.7(CLKOUTA1_N)
N16717223: J13.1 R118.1 U8.27(CLKIN1)
N16717247: J14.1 R118.2 U8.26(CLKIN1_N)
N16717411: J12.1 U8.29(REFOUT)
N16717419: JMP20.2 U8.31(REFOUT_EN)
N16717493: JMP20.1 R120.2
N16719912: J15.B5(SMCLK) R122.2
N16719964: J15.B6(SMDAT) R123.2
N16720088: J15.A11(PERST#) R121.1
N16720136: J15.B12(RSVD10) R125.2
N16724044: J16.B5(SMCLK) R126.2
N16724088: J16.B6(SMDAT) R127.2
N16724220: J16.A11(PERST#) R128.1
N16724224: J16.B11(WAKE#) R129.2
N16724268: J16.B12(RSVD10) R130.2
N16781629: J15.B11(WAKE#) R124.2
N16831338: JMP1.8 R4.2
N16831347: JMP1.6 R3.1
N16831350: JMP1.4 R2.2
N16831359: JMP1.2 R1.2
N16831816: JMP2.8 R8.2
N16831825: JMP2.6 R7.1
N16831828: JMP2.4 R6.2
N16831837: JMP2.2 R5.2
N16831849: JMP3.2 R9.2
N16831858: JMP3.4 R10.2
N16831867: JMP3.6 R11.1
N16831870: JMP3.8 R12.2
N16832723: JMP4.2 R21.2
N16832755: JMP4.4 R22.2
N16832773: JMP4.6 R23.1
N16832779: JMP4.8 R24.2
N16832807: JMP5.2 R25.2
N16832839: JMP5.4 R26.2
N16832857: JMP5.6 R27.1
N16832863: JMP5.8 R28.2
N16832891: JMP6.2 R29.2
N16832923: JMP6.4 R30.2
N16832941: JMP6.6 R39.1
N16832947: JMP6.8 R40.2
N16833662: JMP9.2 R49.2
N16833694: JMP9.4 R50.2
N16833712: JMP9.6 R51.1
N16833718: JMP9.8 R52.2
N16833746: JMP10.2 R53.2
N16833778: JMP10.4 R62.2
N16833796: JMP10.6 R63.1
N16833802: JMP10.8 R64.2
N16833830: JMP11.2 R65.2
N16833862: JMP11.4 R66.2
N16833880: JMP11.6 R67.1
N16833886: JMP11.8 R68.2
N16835436: JMP14.2 R133.2
N16835468: JMP14.4 R134.2
N16835486: JMP14.6 R135.1
N16835492: JMP14.8 R136.2
N16835520: JMP15.2 R137.2
N16835552: JMP15.4 R138.2
N16835570: JMP15.6 R139.1
N16835576: JMP15.8 R140.2
N16835604: JMP16.2 R141.2
N16835636: JMP16.4 R142.2
N16835654: JMP16.6 R143.1
N16835660: JMP16.8 R144.2
N16837171: J30.2 R13.2
N16837180: J30.4 R14.2
N16837189: J30.6 R15.1
N16837198: J30.8 R16.2
N16837577: J23.2 R17.2
N16837609: J23.4 R18.2
N16837629: J23.6 R19.1
N16837647: J23.8 R20.2
N16841214: J24.2 R41.2
N16841246: J24.4 R42.2
N16841266: J24.6 R43.1
N16841284: J24.8 R44.2
N16842142: J25.2 R45.2
N16842174: J25.4 R46.2
N16842194: J25.6 R47.1
N16842212: J25.8 R48.2
N16843638: J26.2 R69.2
N16843670: J26.4 R70.2
N16843690: J26.6 R71.1
N16843708: J26.8 R72.2
N16844326: J27.2 R73.2
N16844358: J27.4 R74.2
N16844378: J27.6 R75.1
N16844396: J27.8 R76.2
N16846395: J28.2 R145.2
N16846427: J28.4 R146.2
N16846447: J28.6 R147.1
N16846465: J28.8 R148.2
N16847091: J29.2 R149.2
N16847123: J29.4 R150.2
N16847143: J29.6 R151.1
N16847161: J29.8 R152.2
N16850880: J1.3 L1.2
N16850966: J2.3 L2.2
N16851615: J3.3 L3.2
N16851807: J4.3 L4.2

Not connected (* = marked no-connect by the designer): J15 A52(TXp8)* A53(TXn8)* A56(TXp9)* A57(TXn9)* A60(TXp10)* A61(TXn10)* A64(TXp11)* A65(TXn11)* A68(TXp12)* A69(TXn12)* A72(TXp13)* A73(TXn13)* A76(TXp14)* A77(TXn14)* A80(TXp15)* A81(TXn15)* B50(RXp8)* B51(RXn8)* B54(RXp9)* B55(RXn9)* B58(RXp10)* B59(RXn10)* B62(RXp11)* B63(RXn11)* B66(RXp12)* B67(RXn12)* B70(RXp13)* B71(RXn13)* B74(RXp14)* B75(RXn14)* B78(RXp15)* B79(RXn15)*; P4 4(7)* 5(3)* 7(4)* 8(9)*; U1 19(RSVD1)*; U2 19(RSVD1)*; U3 19(RSVD1)*; U4 19(RSVD1)*; U6 1(NU)* 2(NU_1)* 3(NU_2)* 6(NC)* 7(NC_1)* 26(NC_2)* 27(NC_3)* 37(RESV_TRK)*; U7 11(4Y)*; U8 11(OSCIN)* 12(OSCOUT)* 18(CLKOUTB1_N)* 19(CLKOUTB1)* 21(CLKOUTB0_N)* 22(CLKOUTB0)* 25(NC)*

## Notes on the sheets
sheet 2
- PCIe CONNECTOR B x16
sheet 3
- HARDWARE PAGE
- FID1
- FID2
- FID3
- FID4
- FID5
- FID6
- Install label  in silkscreened box after
  final wash. Text shall 8 pt font. Text shall
  be per the label table in the PDF Schematic
- Variant / Label Table
- Mounting Hole
- Mounting Hole
- Variant
- Label Text
- 001
- DS320PR412-421EVM
- PCB LOGO
  Texas Instruments
- PCB LOGO
  ESD1
- PCB LOGO
  FCC Disclaimer
- PCB LOGO
  CE LOGO
- PCB LOGO
  WEEE LOGO
sheet 4
- DS320PR412_0
- DS320PR412_1
- PR412_1 VCC
  1 - 2 = PCIe 3.3V
  2 - 3 = Reg 3.3V
- PR412_0 VCC
  1 - 2 = PCIe 3.3V
  2 - 3 = Reg 3.3V
sheet 5
- DS320PR421_3
- DS320PR421_2
- PR421_3 VCC
  1 - 2 = PCIe 3.3V
  2 - 3 = Reg 3.3V
- PR421_2 VCC
  1 - 2 = PCIe 3.3V
  2 - 3 = Reg 3.3V
sheet 6
- 412_0 EQ1
  1-2 = L0
  3-4 = L1
  5-6 = L2
  7-8 = L3
  NC = L4
- 412_0 EQ0_ADDR
  1-2 = L0
  3-4 = L1
  5-6 = L2
  7-8 = L3
  NC = L4
- 412_0 MODE
  1-2 = L0
  3-4 = L1
  5-6 = L2
  7-8 = L3
  NC = L4
- 412_0 RX_DET
  1-2 = L0
  3-4 = L1
  5-6 = L2
  7-8 = L3
  9-10 = SCL
  NC = L4
- 412_0 GAIN
  1-2 = L0
  3-4 = L1
  5-6 = L2
  7-8 = L3
  9-10 = SDA
  NC = L4
- PD
  1-2 = PU
  2-3 = PD
- 412_1 MODE
  1-2 = L0
  3-4 = L1
  5-6 = L2
  7-8 = L3
  NC = L4
- 412_1 EQ1
  1-2 = L0
  3-4 = L1
  5-6 = L2
  7-8 = L3
  NC = L4
- 412_1 EQ0_ADDR
  1-2 = L0
  3-4 = L1
  5-6 = L2
  7-8 = L3
  NC = L4
- PD
- PERST#_INV
- PD
  J22 = PERST#_INV to PD
- 412_1 GAIN
  1-2 = L0
  3-4 = L1
  5-6 = L2
  7-8 = L3
  9-10 = SDA
  NC = L4
- 412_1 RX_DET
  1-2 = L0
  3-4 = L1
  5-6 = L2
  7-8 = L3
  9-10 = SCL
  NC = L4
- 421_2 EQ1
  1-2 = L0
  3-4 = L1
  5-6 = L2
  7-8 = L3
  NC = L4
- 421_2 MODE
  1-2 = L0
  3-4 = L1
  5-6 = L2
  7-8 = L3
  NC = L4
- 421_2 EQ0_ADDR
  1-2 = L0
  3-4 = L1
  5-6 = L2
  7-8 = L3
  NC = L4
- 421_2 GAIN
  1-2 = L0
  3-4 = L1
  5-6 = L2
  7-8 = L3
  9-10 = SDA
  NC = L4
- 421_2 RX_DET
  1-2 = L0
  3-4 = L1
  5-6 = L2
  7-8 = L3
  9-10 = SCL
  NC = L4
- 421_3 MODE
  1-2 = L0
  3-4 = L1
  5-6 = L2
  7-8 = L3
  NC = L4
- 421_3 EQ1
  1-2 = L0
  3-4 = L1
  5-6 = L2
  7-8 = L3
  NC = L4
- 421_3 EQ0_ADDR
  1-2 = L0
  3-4 = L1
  5-6 = L2
  7-8 = L3
  NC = L4
- 421_3 RX_DET
  1-2 = L0
  3-4 = L1
  5-6 = L2
  7-8 = L3
  9-10 = SCL
  NC = L4
- 421_3 GAIN
  1-2 = L0
  3-4 = L1
  5-6 = L2
  7-8 = L3
  9-10 = SDA
  NC = L4
sheet 7
- I2C Controller Mux
- I2C Adapter Select
  1-2 = USB2ANY
  2-3 = Aardvark
- I2C Controller I/F
- JTAG3
  1-3 = Conn A
  1-2, 3-4, 5-6 = Conn A + B
  3-5 = Conn B
- JTAG4
  1-3 = Conn A
  1-2, 3-4, 5-6 = Conn A + B
  3-5 = Conn B
- JTAG5
  1-3 = Conn A
  1-2, 3-4, 5-6 = Conn A + B
  3-5 = Conn B
- JTAG1
  1-3 = Conn A
  1-2, 3-4, 5-6 = Conn A + B
  3-5 = Conn B
- JTAG2
  1-3 = Conn A
  1-2, 3-4, 5-6 = Conn A + B
  3-5 = Conn B
sheet 8
- POWER
- Route VOSNS to PCIe Connector A
- +3.3V
  1 = 3.3V
  2 = GND
- +12V
  1 = 12V
  2 = GND
- PWRGOOD
- +3.3V
sheet 9
- PCIe EDGE FINGER CONNECTOR
- PERST#
  1-3 = PERST# to PERST# A
  3-5 = PERST# to PERST# B
  1-2 + 3-4 + 5-6 = PERST# to PERST# A & B
- PRSNT2_1
  1-2 = Conn A
  3-4 = Conn B
  5-6 = GND
- PRSNT2_2
  1-2 = Conn A
  3-4 = Conn B
  5-6 = GND
- PRSNT2_3
  1-2 = Conn A
  3-4 = Conn B
  5-6 = GND
- PRSNT2_4
  1-2 = Conn A
  3-4 = Conn B
  5-6 = GND
sheet 10
- CLKOUT_EN
  1-2 = Disabled
  2-3 = Enabled
- CLKIN_SEL0
  1-2 = CLKin1
  2-3 = CLKin0
- CLKIN1+
- REFOUT
- CLKIN1-
- REFOUT_EN
  1-2 = REFOUT
  2-3 = REFOUT Disable
sheet 11
- PCIe CONNECTOR A x8 ONLY
